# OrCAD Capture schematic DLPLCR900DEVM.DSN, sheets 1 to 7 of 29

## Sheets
1 P28-External Parallel Connector: size A3
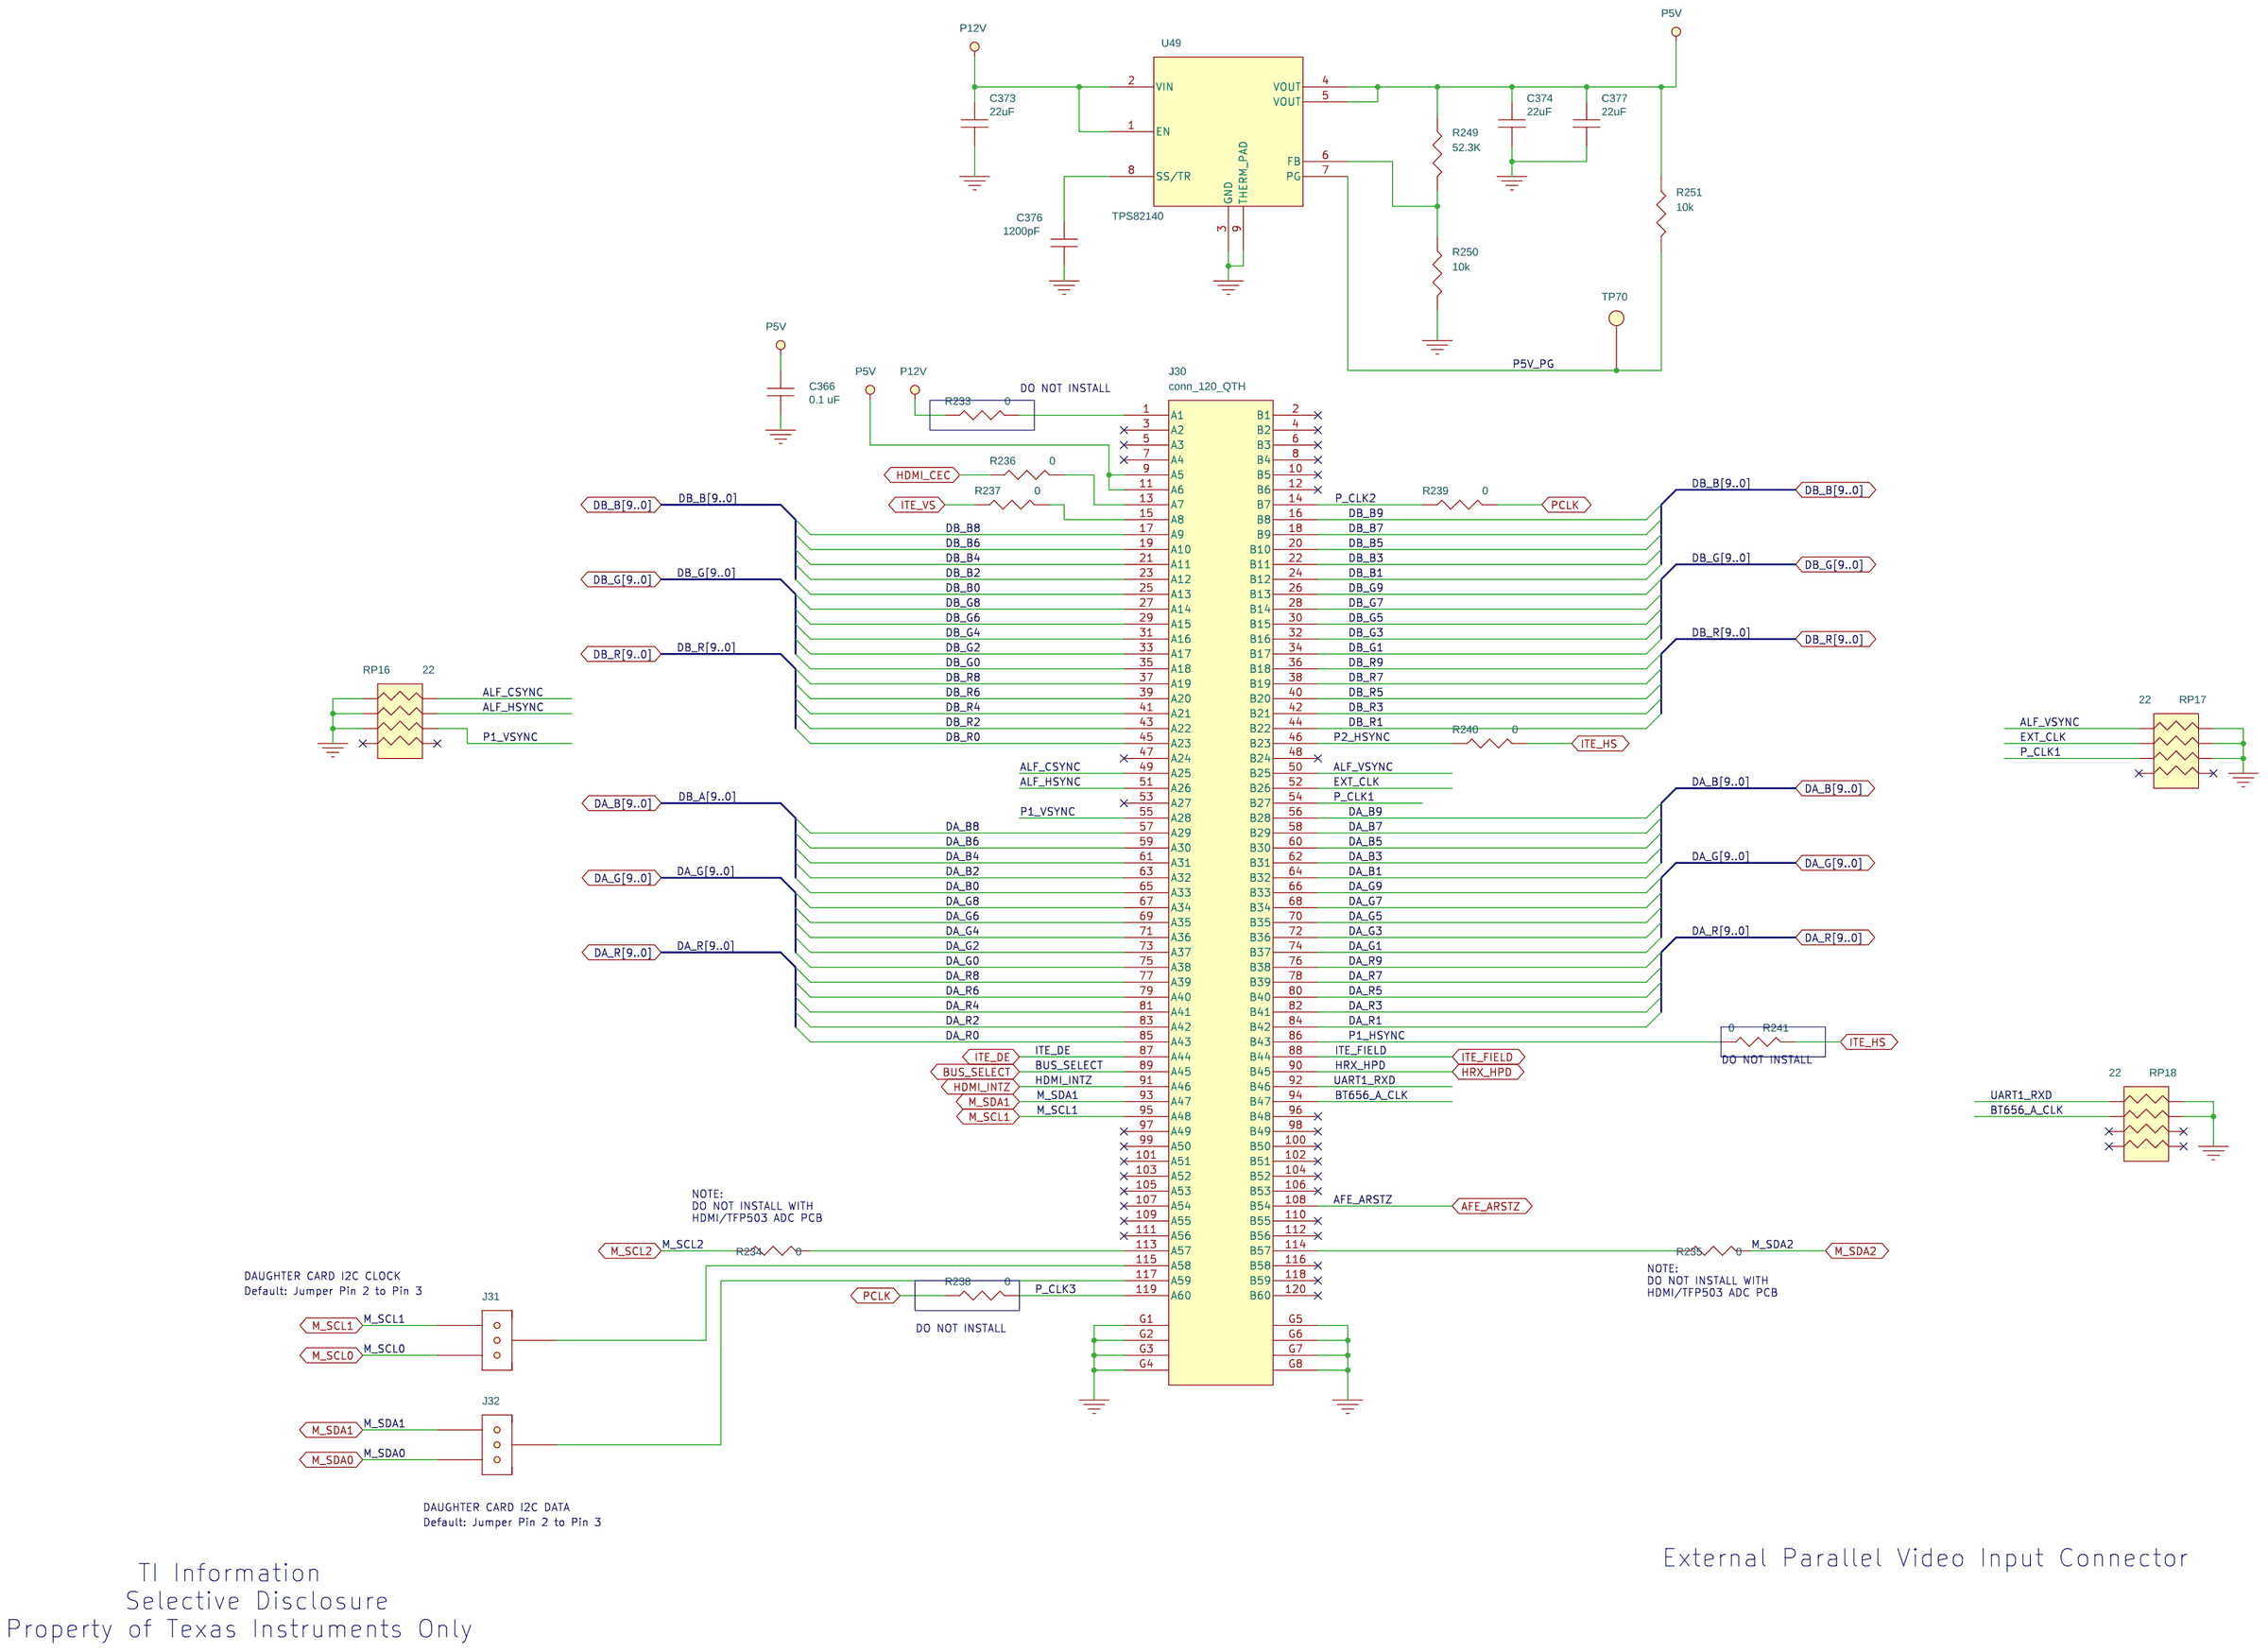
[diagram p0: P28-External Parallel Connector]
2 P02-Import Notice
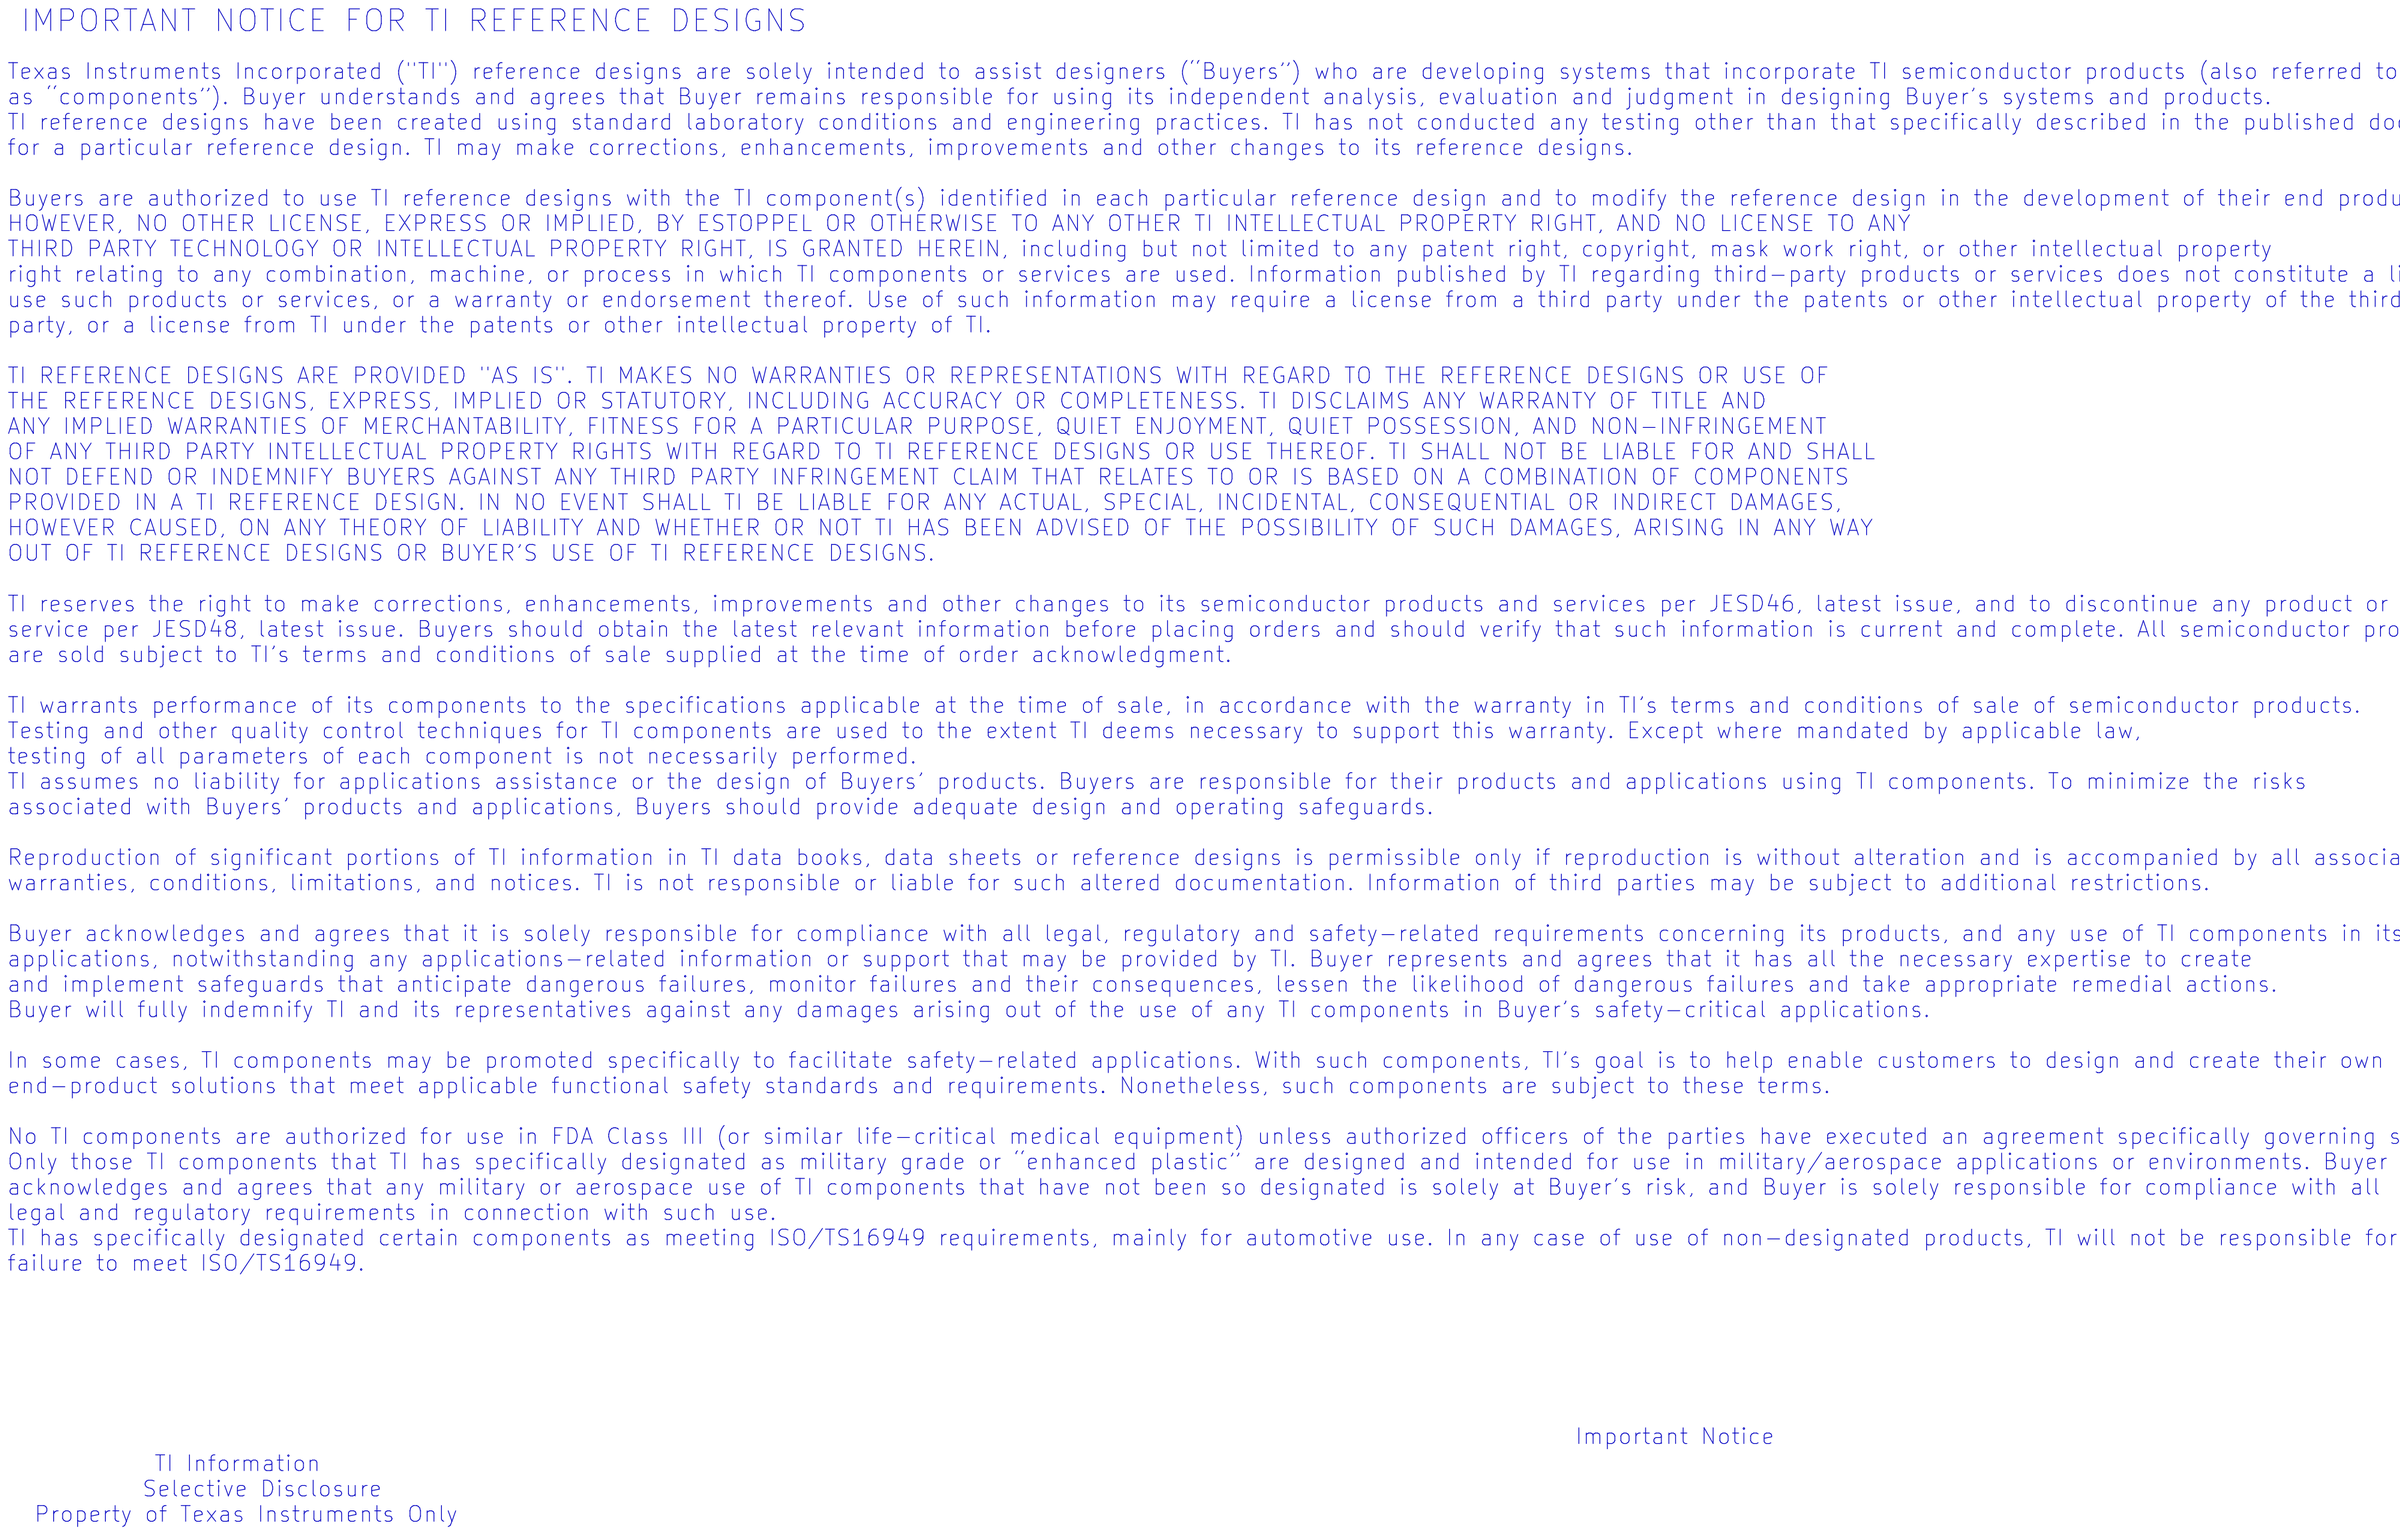
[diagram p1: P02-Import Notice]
3 P25-Power VCCIO & LDO: size A3
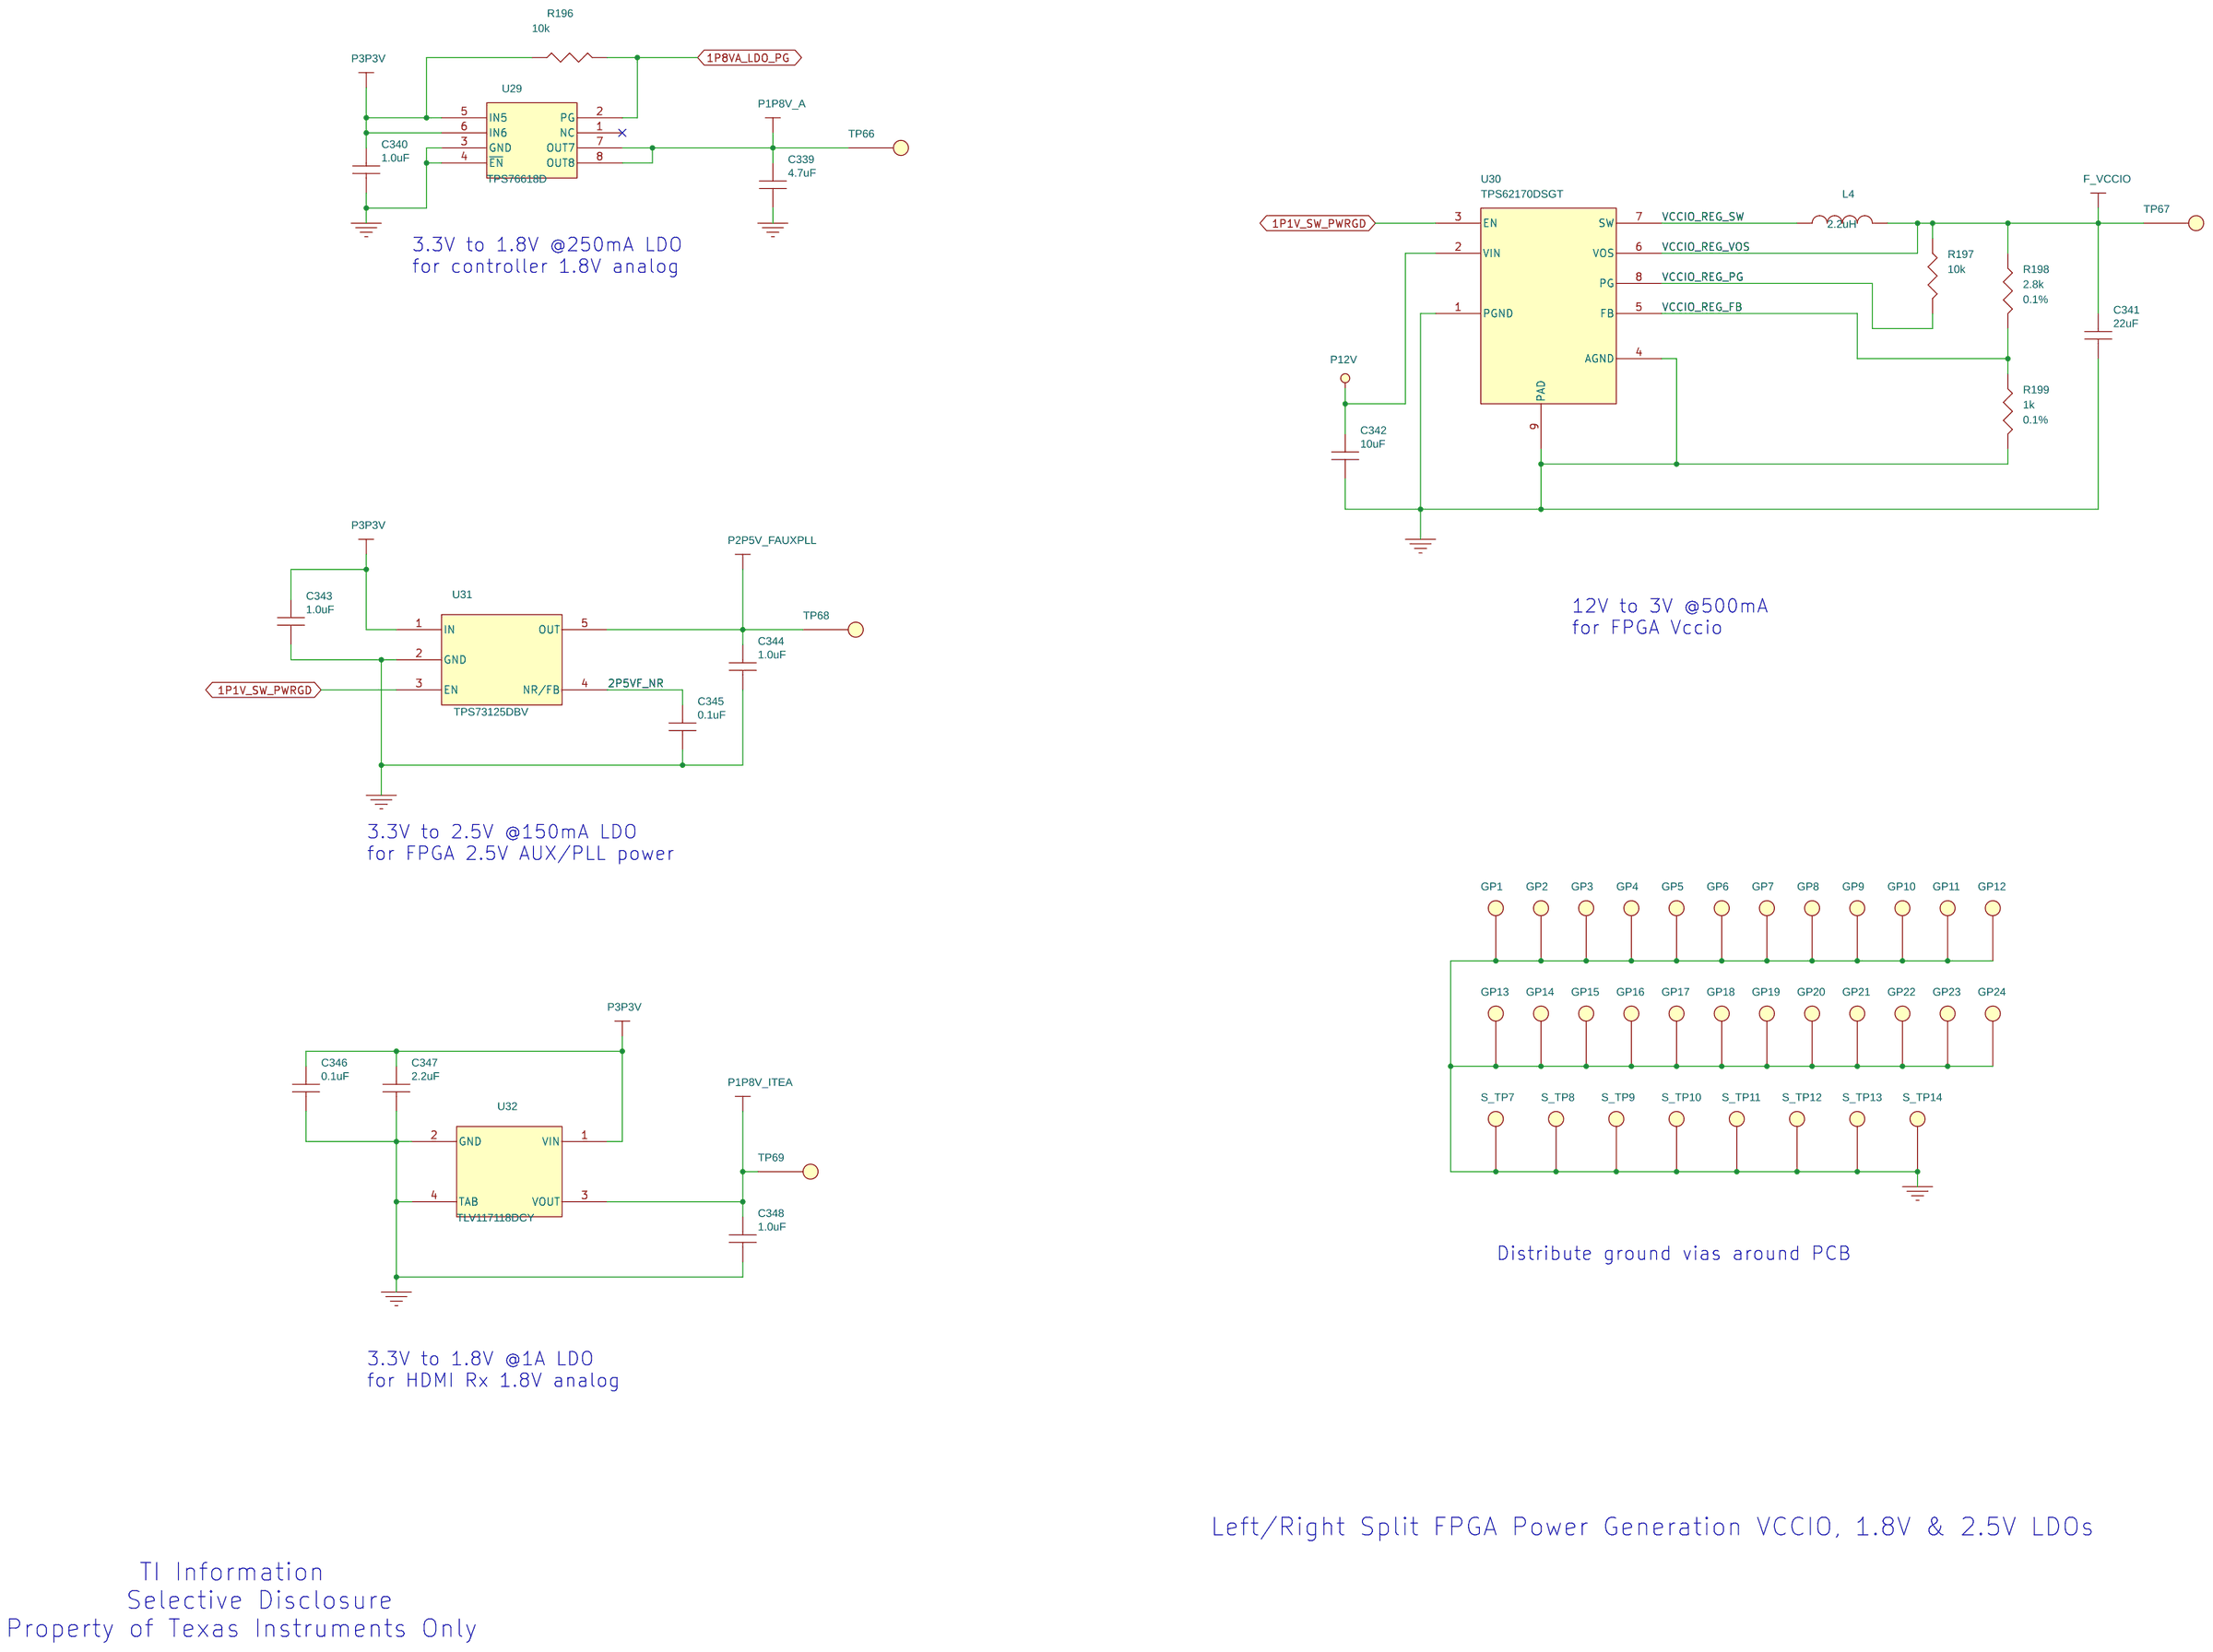
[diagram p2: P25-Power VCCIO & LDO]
4 P10-FPGA Config: size A3
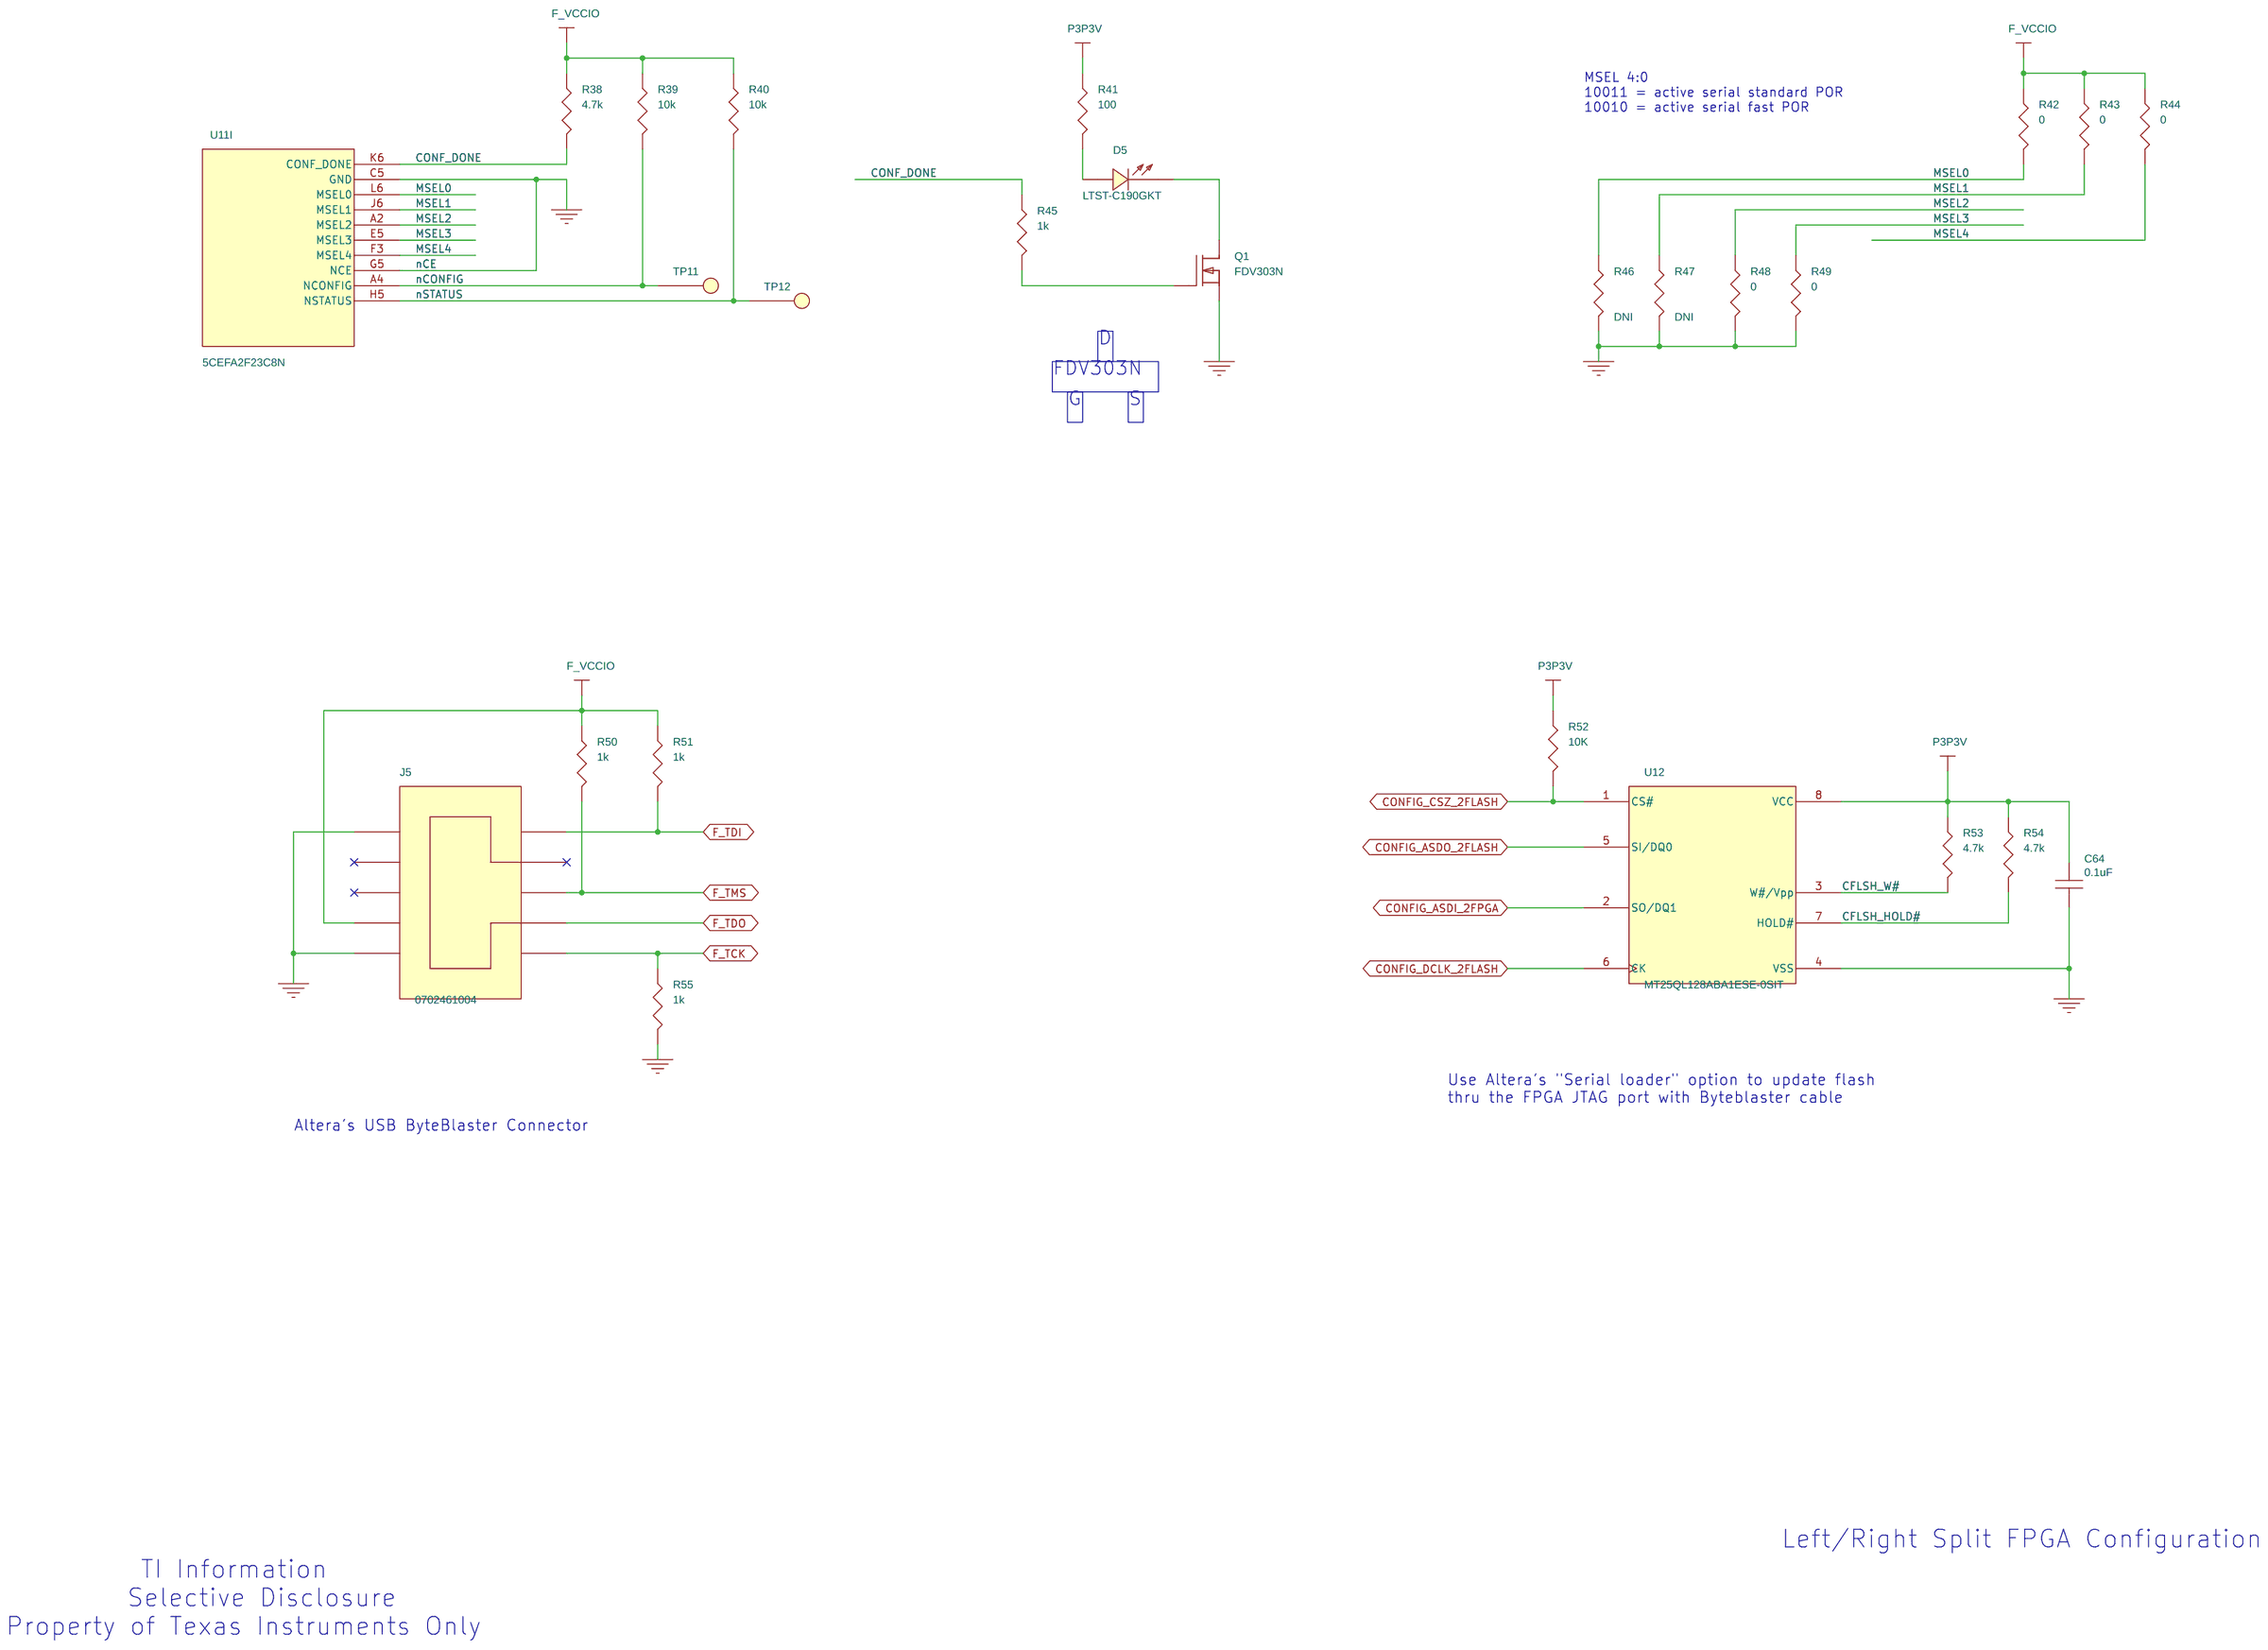
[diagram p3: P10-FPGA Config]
5 P09-FPGA Bank 5A,5B,7A,8A: size A3
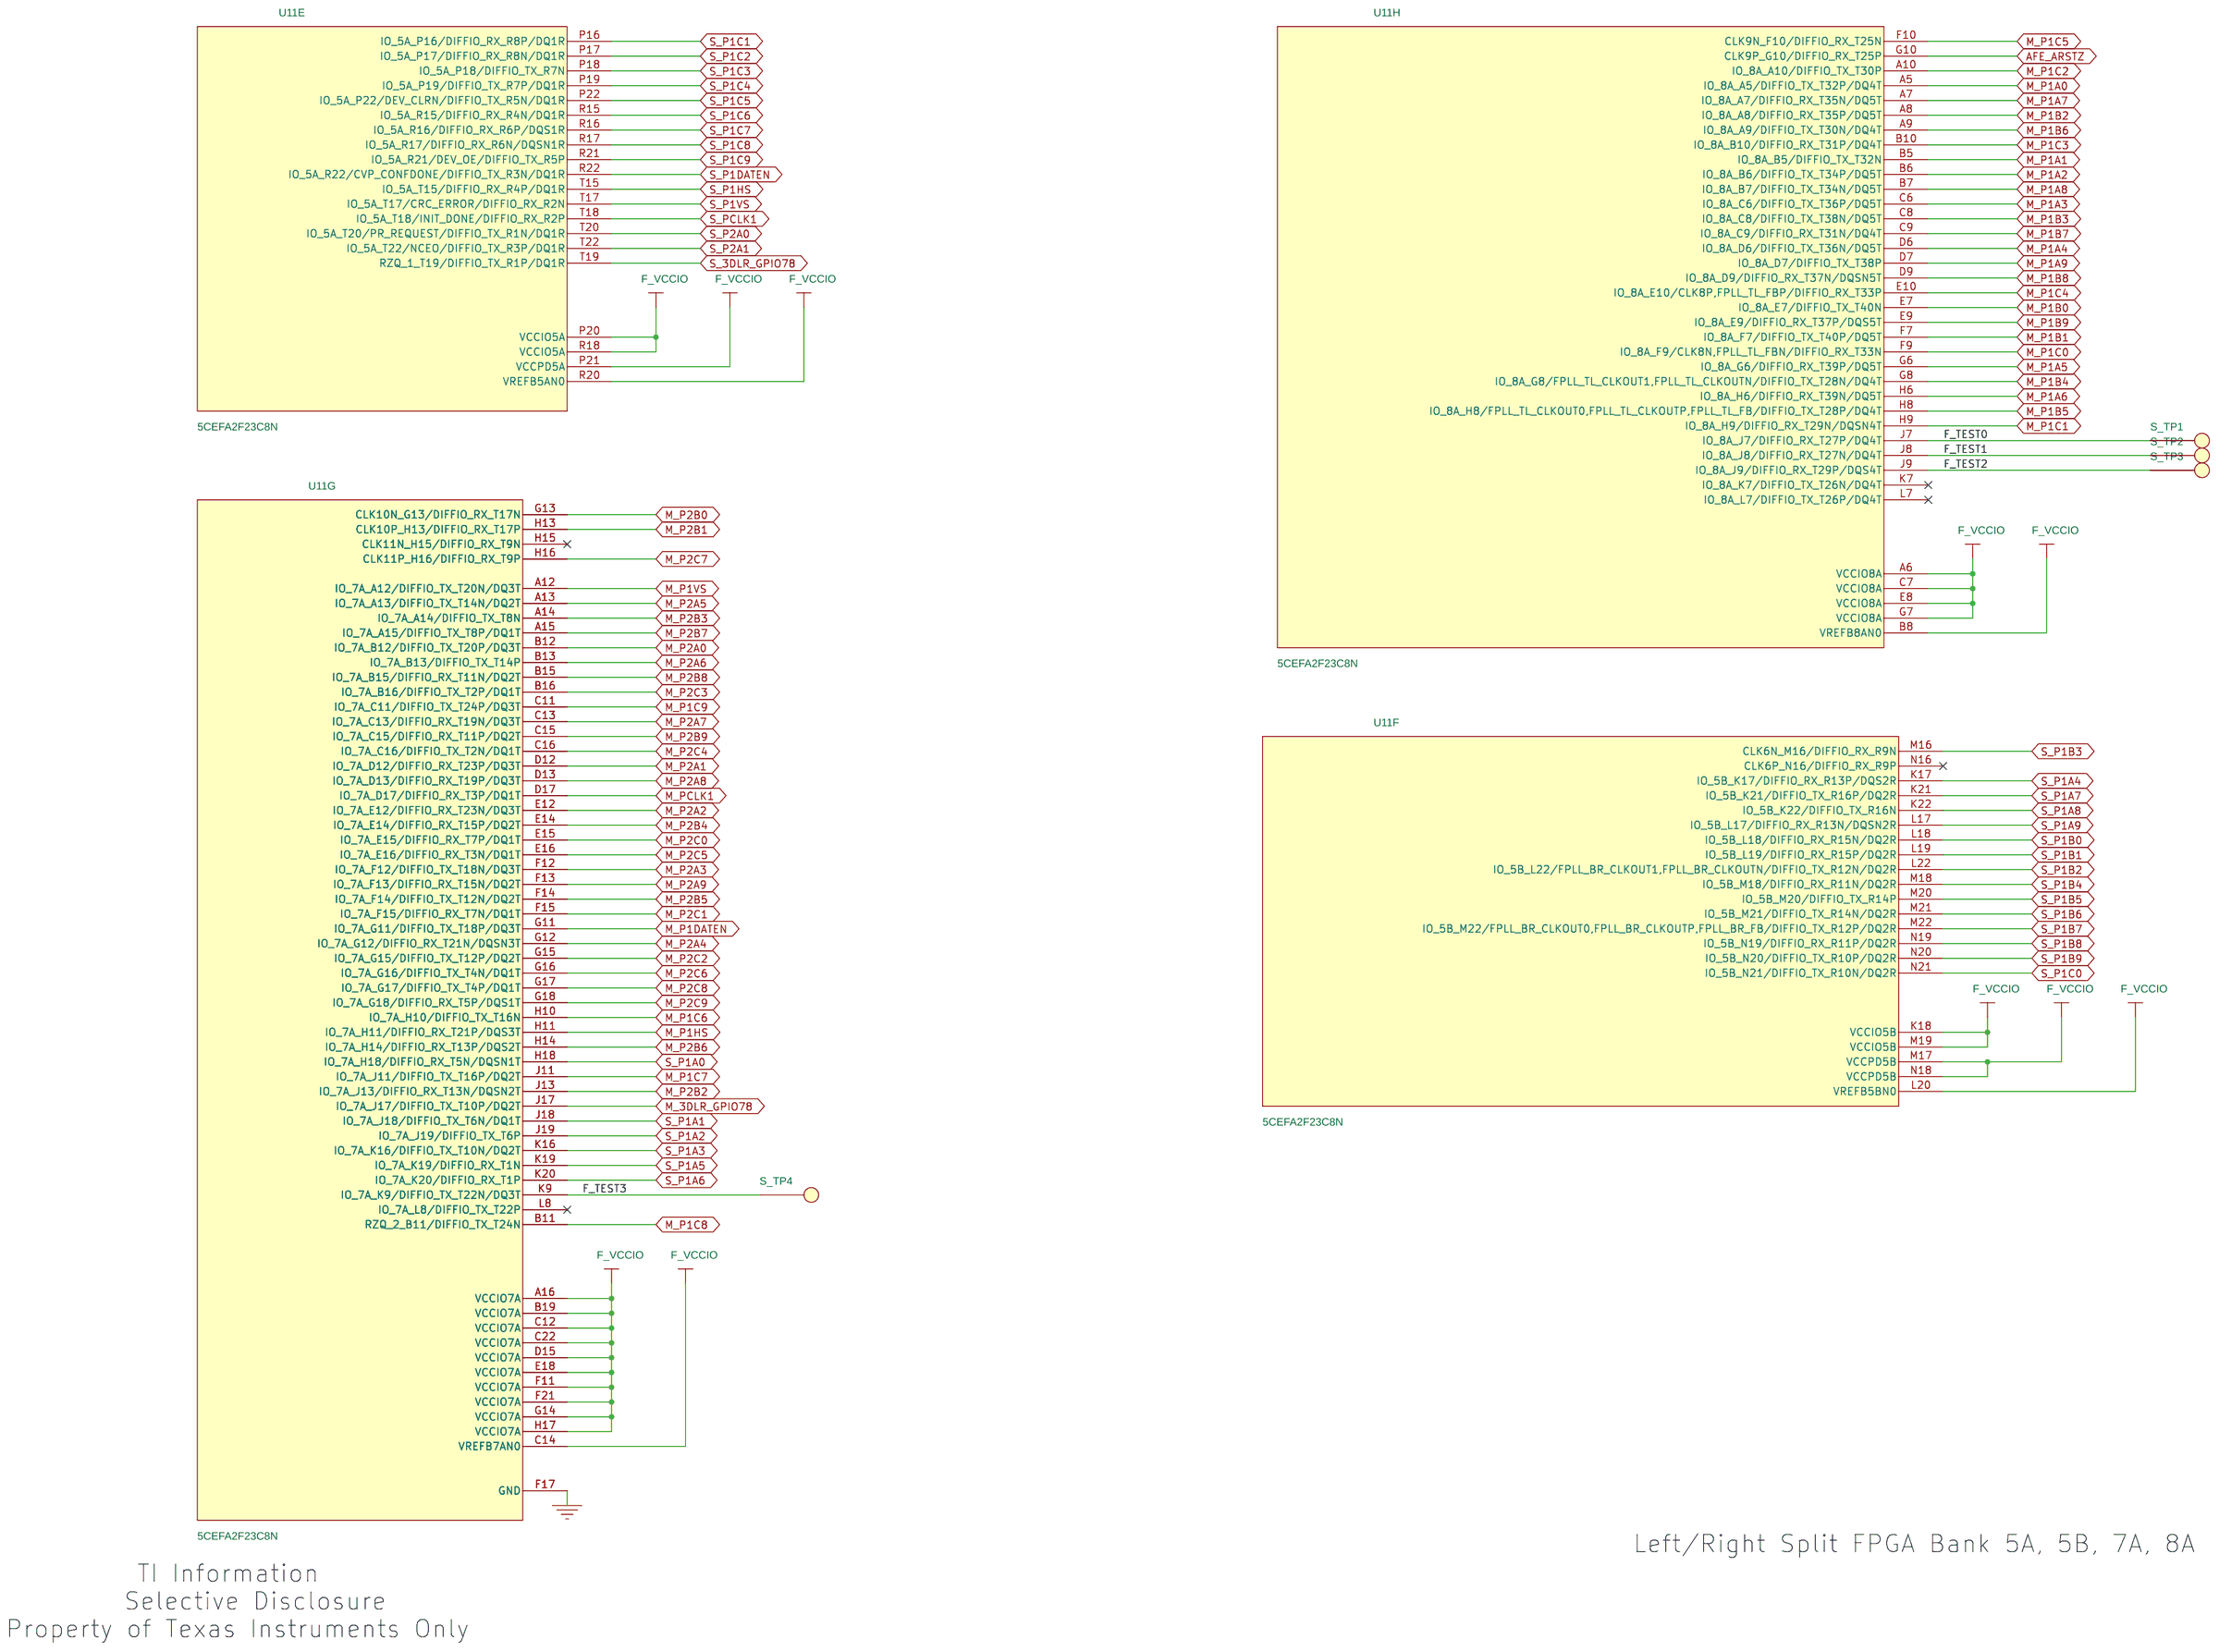
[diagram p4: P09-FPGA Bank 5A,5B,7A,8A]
6 P08-FPGA Bank 2A,3A,3B,4A: size A3
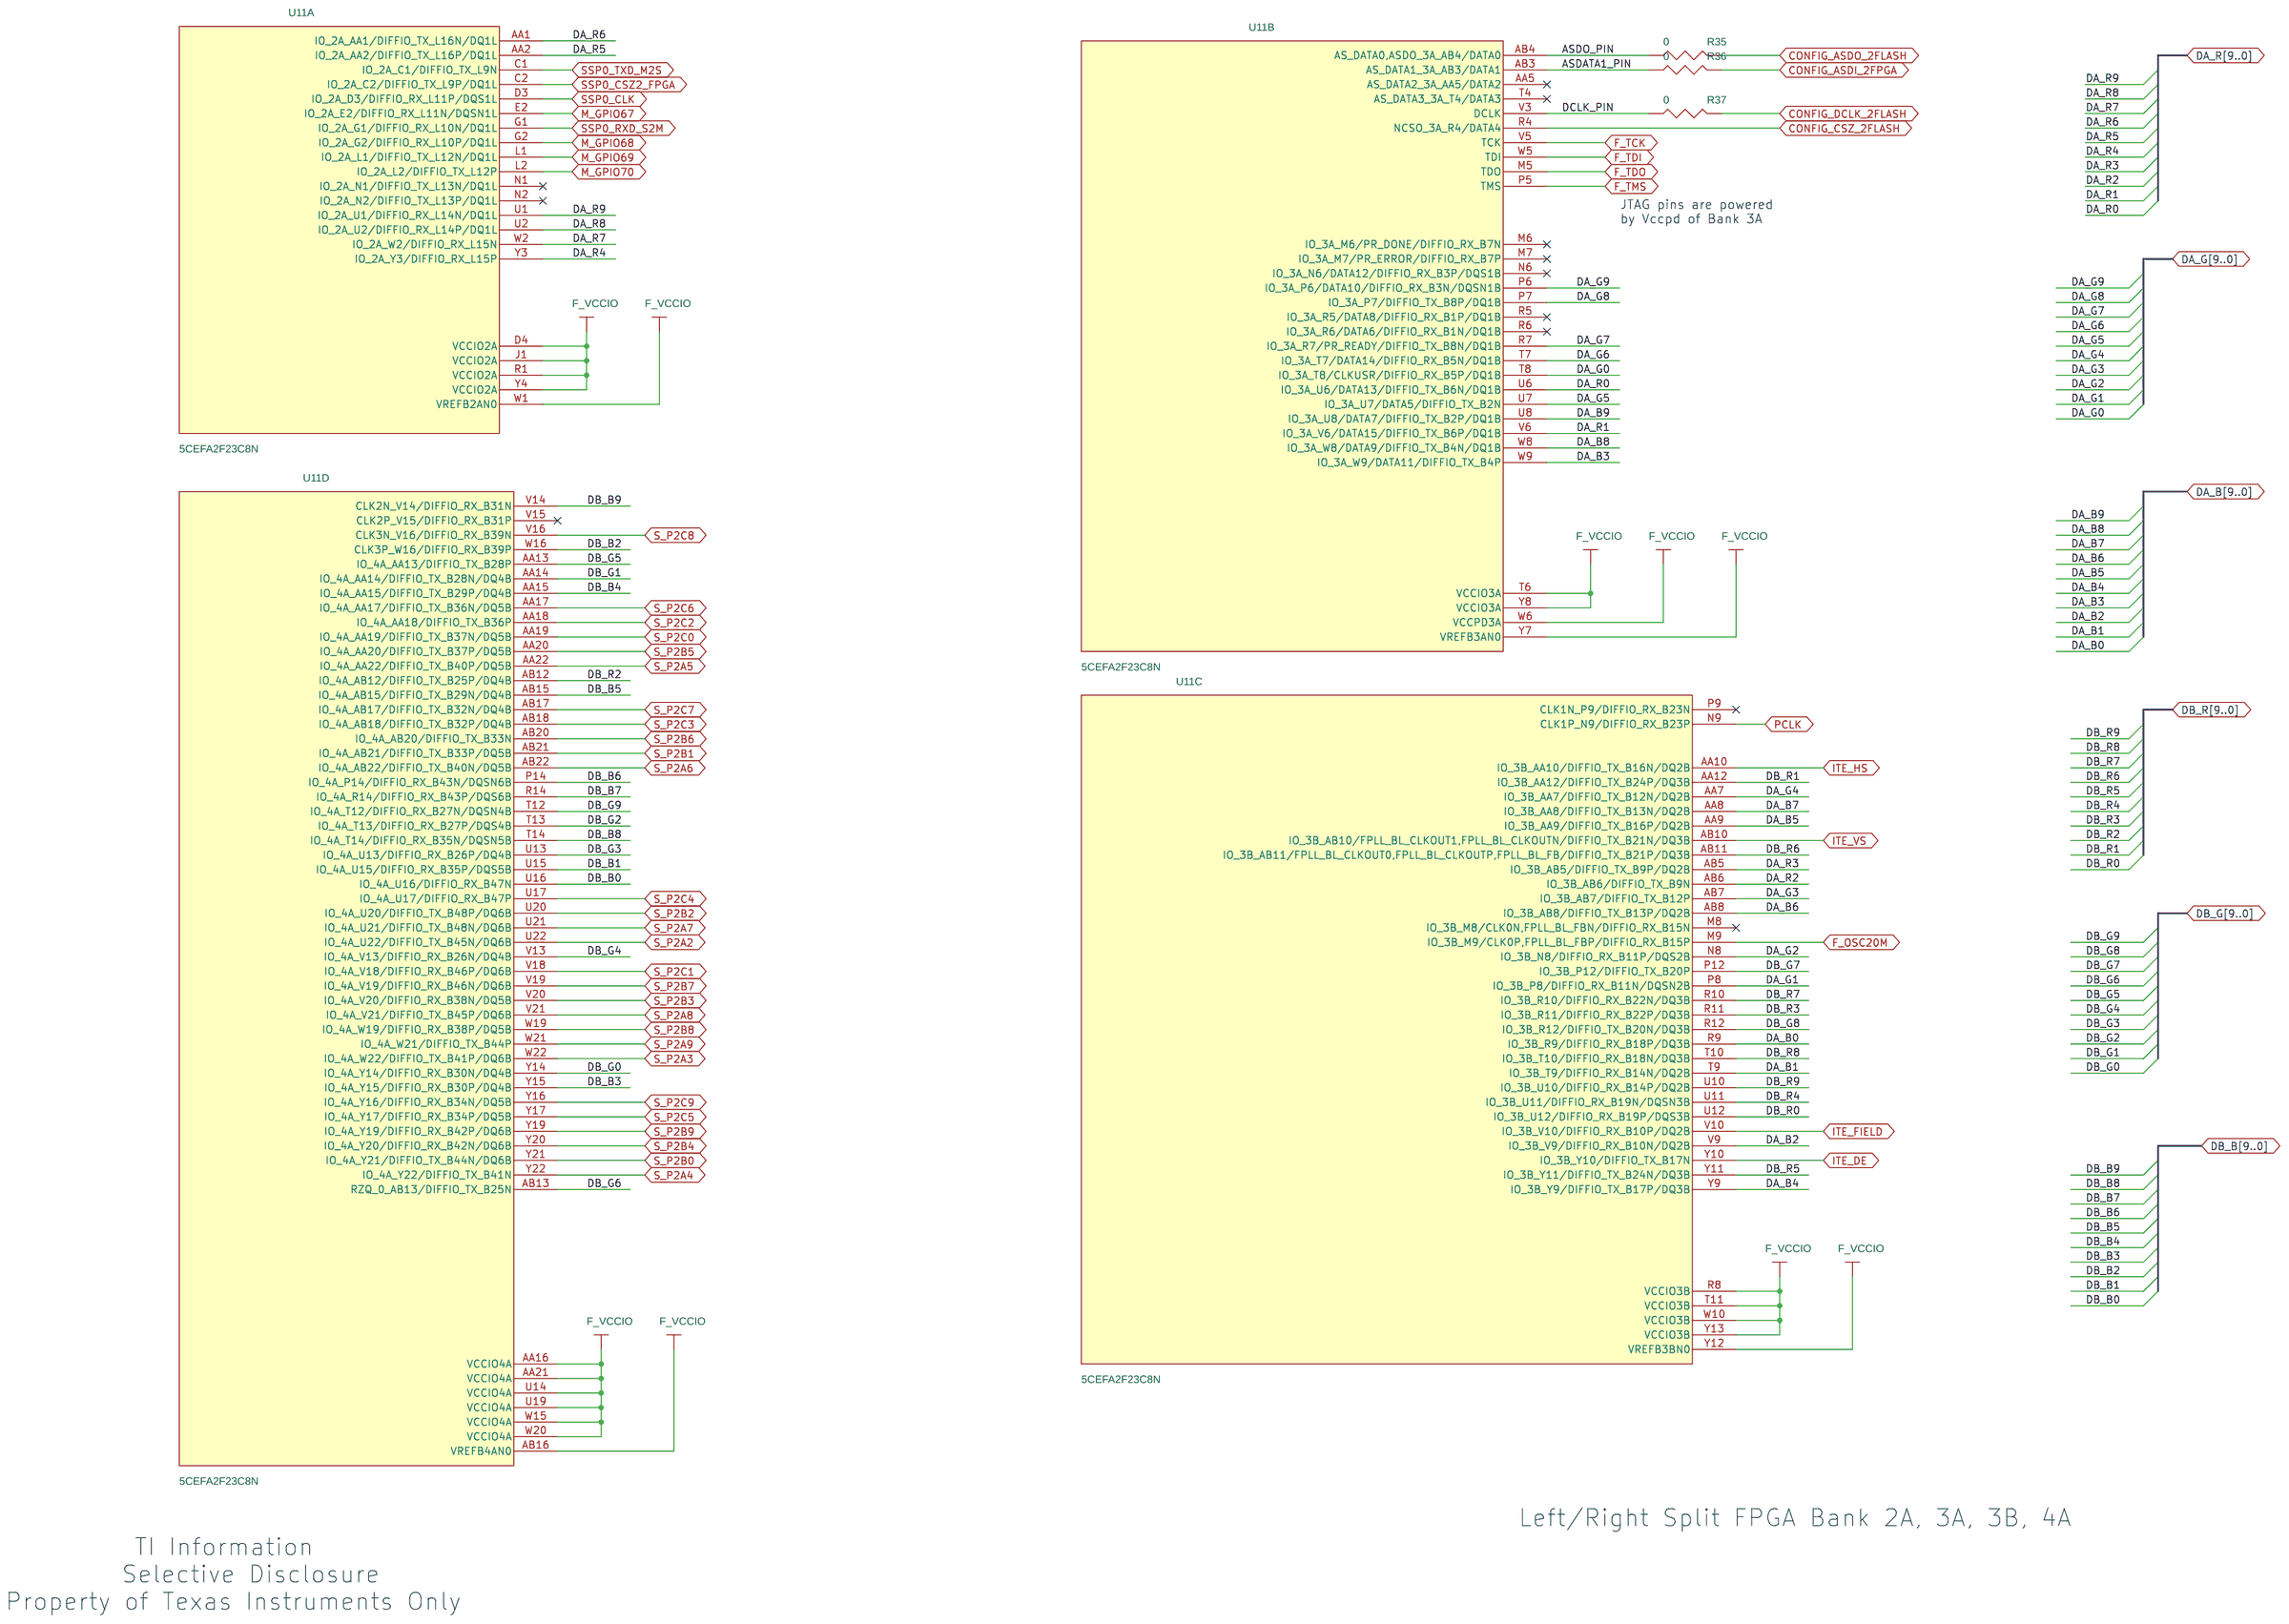
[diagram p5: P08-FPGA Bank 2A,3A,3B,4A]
7 P24-Power 1.1V, 1.8V, 3.3V: size A3
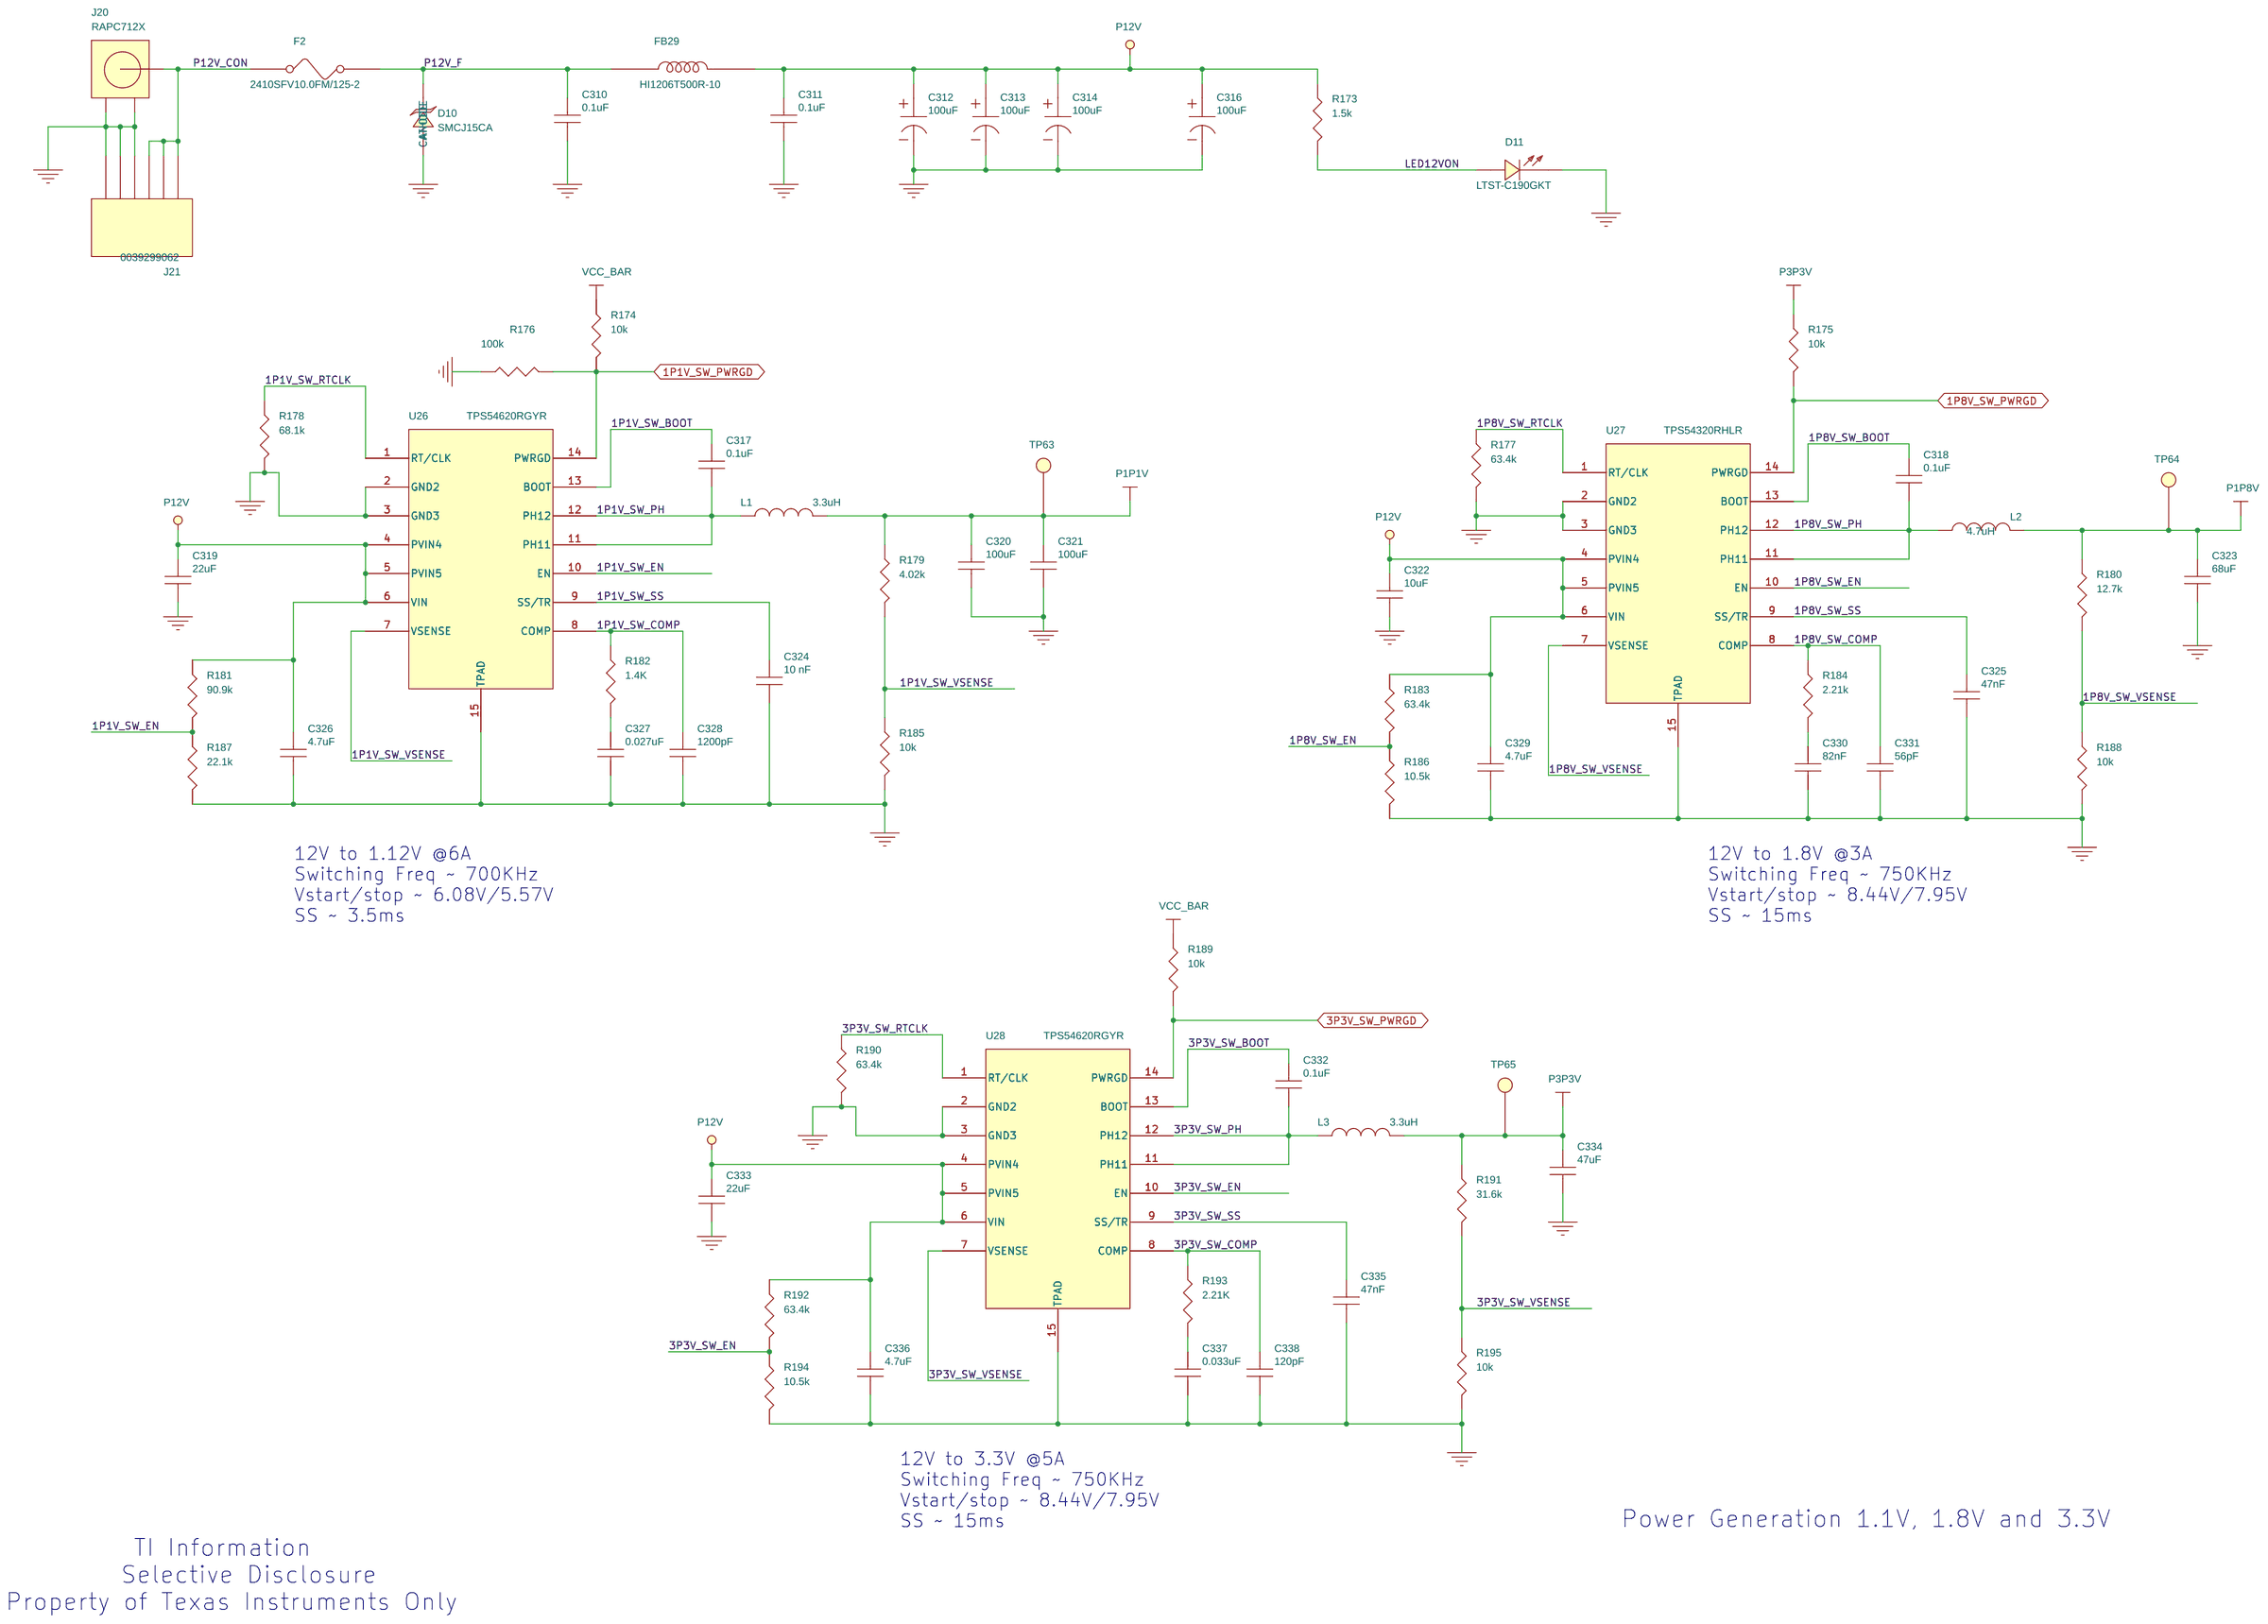
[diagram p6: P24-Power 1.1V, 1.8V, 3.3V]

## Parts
sheet P08-FPGA Bank 2A,3A,3B,4A
R35  0  [0603]
R36  0  [0603]
R37  0  [0603]
sheet P09-FPGA Bank 5A,5B,7A,8A
S_TP1  SMD_Testpoint  [5015pad]
S_TP2  SMD_Testpoint  [5015pad]
S_TP3  SMD_Testpoint  [5015pad]
S_TP4  SMD_Testpoint  [5015pad]
sheet P10-FPGA Config
C64  0.1uF  [0402]
D5  LTST-C190GKT  [0603]
J5  0702461004  [10POS-2ROWS-2p54mm]
Q1  FDV303N  [SOT-23]
R38  4.7k  [0402]
R39  10k  [0402]
R40  10k  [0402]
R41  100  [0603]
R42  0  [0402]
R43  0  [0402]
R44  0  [0402]
R45  1k  [0402]
R46  DNI  [0402]
R47  DNI  [0402]
R48  0  [0402]
R49  0  [0402]
R50  1k  [0402]
R51  1k  [0402]
R52  10K  [0402]
R53  4.7k  [0402]
R54  4.7k  [0402]
R55  1k  [0402]
TP11  Testpoint  [24mil-plated]
TP12  Testpoint  [24mil-plated]
U11  5CEFA2F23C8N  [F484]  (sections A,B,C,D,E,F,G,H,I,J,K)
U12  MT25QL128ABA1ESE-0SIT  [SO8W]
sheet P24-Power 1.1V, 1.8V, 3.3V
C310  0.1uF  [0402]
C311  0.1uF  [0402]
C312  100uF  [2312]
C313  100uF  [2312]
C314  100uF  [2312]
C316  100uF  [2312]
C317  0.1uF  [0402]
C318  0.1uF  [0402]
C319  22uF  [1206]
C320  100uF  [1206]
C321  100uF  [1206]
C322  10uF  [0805]
C323  68uF  [1206]
C324  10 nF  [4002]
C325  47nF  [0402]
C326  4.7uF  [0805]
C327  0.027uF  [0402]
C328  1200pF  [0402]
C329  4.7uF  [0805]
C330  82nF  [0603]
C331  56pF  [0402]
C332  0.1uF  [0402]
C333  22uF  [1206]
C334  47uF  [1210]
C335  47nF  [0402]
C336  4.7uF  [0805]
C337  0.033uF  [0402]
C338  120pF  [0402]
D10  SMCJ15CA  [PN_DIODE]
D11  LTST-C190GKT  [0603]
F2  2410SFV10.0FM/125-2  [2410]
FB29  HI1206T500R-10  [1206]
J20  RAPC712X  [PAPC712Xthruhole]
J21  0039299062  [2x3_4p2mm_thruhole]
L1  3.3uH  [5x5mm]
L2  4.7uH  [4x4mm]
L3  3.3uH  [4x4mm]
R173  1.5k  [0603]
R174  10k  [0402]
R175  10k  [0603]
R176  100k  [0603]
R177  63.4k  [0402]
R178  68.1k  [0402]
R179  4.02k  [0402]
R180  12.7k  [0603]
R181  90.9k  [0402]
R182  1.4K  [0603]
R183  63.4k  [0402]
R184  2.21k  [0402]
R185  10k  [0402]
R186  10.5k  [0402]
R187  22.1k  [0402]
R188  10k  [0402]
R189  10k  [0402]
R190  63.4k  [0402]
R191  31.6k  [0402]
R192  63.4k  [0402]
R193  2.21K  [0402]
R194  10.5k  [0402]
R195  10k  [0402]
TP63  Testpoint  [24mil-plated]
TP64  Testpoint  [24mil-plated]
TP65  Testpoint  [24mil-plated]
U26  TPS54620RGYR  [14-VFQFN]
U27  TPS54320RHLR  [14-VFQFN]
U28  TPS54620RGYR  [14-VFQFN]
sheet P25-Power VCCIO & LDO
C339  4.7uF  [0603]
C340  1.0uF  [0402]
C341  22uF  [0805]
C342  10uF  [0805]
C343  1.0uF  [0402]
C344  1.0uF  [0402]
C345  0.1uF  [0402]
C346  0.1uF  [0402]
C347  2.2uF  [0603]
C348  1.0uF  [0402]
GP1  Ground point  [24mil-plated]
GP2  Ground point  [24mil-plated]
GP3  Ground point  [24mil-plated]
GP4  Ground point  [24mil-plated]
GP5  Ground point  [24mil-plated]
GP6  Ground point  [24mil-plated]
GP7  Ground point  [24mil-plated]
GP8  Ground point  [24mil-plated]
GP9  Ground point  [24mil-plated]
GP10  Ground point  [24mil-plated]
GP11  Ground point  [24mil-plated]
GP12  Ground point  [24mil-plated]
GP13  Ground point  [24mil-plated]
GP14  Ground point  [24mil-plated]
GP15  Ground point  [24mil-plated]
GP16  Ground point  [24mil-plated]
GP17  Ground point  [24mil-plated]
GP18  Ground point  [24mil-plated]
GP19  Ground point  [24mil-plated]
GP20  Ground point  [24mil-plated]
GP21  Ground point  [24mil-plated]
GP22  Ground point  [24mil-plated]
GP23  Ground point  [24mil-plated]
GP24  Ground point  [24mil-plated]
L4  2.2uH  [4x4mm]
R196  10k  [0603]
R197  10k  [0402]
R198  2.8k  [0402]
R199  1k  [0603]
S_TP7  SMD_Testpoint  [5015pad]
S_TP8  SMD_Testpoint  [5015pad]
S_TP9  SMD_Testpoint  [5015pad]
S_TP10  SMD_Testpoint  [5015pad]
S_TP11  SMD_Testpoint  [5015pad]
S_TP12  SMD_Testpoint  [5015pad]
S_TP13  SMD_Testpoint  [5015pad]
S_TP14  SMD_Testpoint  [5015pad]
TP66  Testpoint  [24mil-plated]
TP67  Testpoint  [24mil-plated]
TP68  Testpoint  [24mil-plated]
TP69  Testpoint  [24mil-plated]
U29  TPS76618D  [8SOIC]
U30  TPS62170DSGT  [8WSON]
U31  TPS73125DBV  [SOT23-5]
U32  TLV117118DCY  [SOT223]
sheet P28-External Parallel Connector
C366  0.1 uF  [0402]
C373  22uF  [1206]
C374  22uF  [1206]
C376  1200pF  [0402]
C377  22uF  [1206]
J30  conn_120_QTH  [CONN120-QTH_SAMTEC]
J31  JUMPER-1x3  [CONN3-TMM-103-02-G-S_SAM]
J32  JUMPER-1x3  [CONN3-TMM-103-02-G-S_SAM]
R233  0  [0402]
R234  0  [0402]
R235  0  [0402]
R236  0  [0402]
R237  0  [0402]
R238  0  [0402]
R239  0  [0402]
R240  0  [0402]
R241  0  [0402]
R249  52.3K  [0402]
R250  10k  [0402]
R251  10k  [0402]
RP16  22  [0804]
RP17  22  [0804]
RP18  22  [0804]
TP70  Testpoint  [24mil-plated]
U49  TPS82140  [SOIC8-SIL0008D_TI]

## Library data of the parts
R35-R37 = 0.0_OHM_1_10W_0603
S_TP1-S_TP4 S_TP7-S_TP14 = SMD_Testpoint
C64 = CER_0.1UF_16V_10%_X5R_0402: MFG: Samsung; MFG Part Number: CL05A104KO5NNNC
D5 D11 = LED_GREEN_CLEAR_0603
J5 = 10POS_2ROWS_2.54MM_VERT
Q1 = FDV303N_MOSFET_N
R38 R53 R54 = 4.7K_OHM_1_10W_5%_0402
R39 R40 R46 R47 R52 R174 R189 R197 = 10K_OHM_1_10W_5%_0402
R41 = 100_OHM_1_10W_5%_0603
R42-R44 R48 R49 = 0.0_OHM_1_10W_0402
R45 R50 R51 R55 = 1.0K_OHM_1_16W_5%_0402
TP11 TP12 TP63-TP70 = Testpoint
U11 = FPGA_Cyclone5_5CEFA2F23C8N
U12 = Flash_N25Q_SPI_3.3V_32Mb_8SOW
C310 C311 = CER_0.1UF_50V_10%_X7R_0402: MFG: Samsung; MFG Part Number: CL05A104KO5NNNC
C312-C314 C316 = TANT_100UF_25V_10%_2917: MFG Part Number: T491X107K025AT
C317 C318 C332 C345 C346 = CER_0.1UF_25V_10%_X5R_0402
C319 C333 C373 C374 C377 = CER_22UF_25V_10%_X5R_1206: MFG: Samsung; MFG Part Number: CL31A226KAHNNNE
C320 C321 = CER_100UF_6.3V_20%_X5R_1206
C322 C342 = CER_10UF_25V_10%_X5R_0805
C323 = CER_68UF_10V_20%_X5R_1206
C324 = CER_10_nF_25V_10%_X5R_0402: MFG: Samsung; MFG Part Number: CL05B103KA5NNNC
C325 C335 = CER_0.047UF_16V_10%_X7R_0402
C326 C329 C336 = CER_4.7UF_50V_10%_X5R_0805
C327 = CER_0.027UF_16V_10%_X5R_0402
C328 C376 = CER_1200PF_50V_10%_X7R_0402
C330 = CER_0.082UF_50V_10%_X7R_0603
C331 = CER_56PF_50V_5%_NPO_0402
C334 = CER_47UF_16V_20%_X5R_1210
C337 = CER_0.033UF_16V_10%_X7R_0402
C338 = CER_120PF_50V_5%_NP0_0402
D10 = DIODE_TVS
F2 = FUSE_10A_125V_FAST_2410
FB29 = HI1206T500R-10_6A_50_OHM_1206
J20 = CON_PWRJACK3_RAPC712
J21 = PWR_CONN_HEADER_6POS_4.2MM_VERT
L1 = INDUCTOR_3.3UH_8.7A_20%
L2 = INDUCTOR_4.7UH_4.5A_20%
L3 = INDUCTOR_3.3UH_5.5A_20%
R173 = 1.5K_OHM_1_10W_5%_0603
R175 R196 = 10K_OHM_1_10W_5%_0603
R176 = 100K_OHM_1_10W_1%_0603
R177 R183 R190 R192 = 63.4K_OHM_1_10W_1%_0402
R178 = 68.1K_OHM_1_10W_1%_0402
R179 = 4.02K_OHM_1_10W_.1%_0402
R180 = 12.7K_OHM_1_10W_.1%_0603
R181 = 90.9K_OHM_1_10W_1%_0402
R182 = 1.4K_OHM_1_10W_1%_0603
R184 R193 = 2.21K_OHM_1_10W_1%_0402
R185 R188 R195 R250 R251 = 10K_OHM_1_16W_.1%_0402
R186 R194 = 10.5K_OHM_1_10W_1%_0402
R187 = 22.1K_OHM_1_10W_1%_0402
R191 = 31.6K_OHM_1_16W_.1%_0402
U26 U28 = TPS54620
U27 = TPS54320
C339 = CER_4.7UF_16V_20%_X5R_0603
C340 C343 C344 C348 = CER_1.0UF_16V_10%_X5R_0402: MFG: KEMET; MFG Part Number: C0402C105M4PAC7867
C341 = CER_22UF_16V_10%_X5R_0805
C347 = CER_2.2UF_25V_10%_X5R_0603
GP1-GP24 = Ground_point
L4 = INDUCTOR_2.2UH_XFL4020
R198 = 2.8K_OHM_1_16W_.1%_0402: Tolerance: 0.1%
R199 = 1.0K_OHM_1_10W_.1%_0603: Tolerance: 0.1%
U29 = TPS76618_REG_LDO_1.8V_0.25A
U30 = TPS62170_BUCK_SYNC_ADJ_0.5A
U31 = TPS73125DBV_LDO_2.5V_0.15A
U32 = TLV117118DCY_LDO_1.8V_1A_SOT223
C366 = CAP_NP: Capacitor; MFG: KEMET; MFG Part Number: C0402C104K8RACTU; Part Number: C0402C104K8RACTU; RATING: 10V; SOURCE: DIGI 399-3520-1-ND; TOLERANCE: 10%; Type: X7R
J30 = conn_120_QTH: Connector, 120 pin; MFG: SAMTEC; MFG Part Number: QTH-060-05-F-D-A; Part Number: QTH-060-05-F-D-A; SOURCE: SAMTEC
J31 J32 = JUMPER-1x3: Jumper, 1x3; MFG: HARWIN; MFG Part Number: M22-2510305; Part Number: M22-2510305; SOURCE: DIGI 952-1312-ND
R233 R238 R241 = R: Resistor; DNI: DNI; ICA_MFR_NAME: PANASONIC; ICA_PARTNUM: $$1785048$$ERJ-3GSYJ102; MFG: PANASONIC; MFG Part Number: ERJ-2GE0R00X; Part Number: ERJ-2GE0R00X; RATING: 1/10W; SOURCE: DIGI P0.0JCT-ND
R234-R237 R239 R240 = R: Resistor; ICA_MFR_NAME: PANASONIC; ICA_PARTNUM: $$1785048$$ERJ-3GSYJ102; MFG: PANASONIC; MFG Part Number: ERJ-2GE0R00X; Part Number: ERJ-2GE0R00X; RATING: 1/10W; SOURCE: DIGI P0.0JCT-ND
R249 = 10K_OHM_1_16W_.1%_0402: MFG Part Number: ERJ-2RKF5232X; Rating: 1/10W; TOLERANCE: 1%
RP16-RP18 = 22_OHM_ARR_1_32W_5%_0804
U49 = TPS82140: MFG: Texas Instruments; MFG Part Number: TPS82140SILR; PART NUMBER: TPS82140SILR

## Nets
GND: C64.2 C310.2 C311.2 C312.2 C313.2 C314.2 C316.2 C319.2 C320.2 C321.2 C322.2 C323.2 C324.2 C325.2 C326.2 C327.2 C328.2 C329.2 C330.2 C331.2 C333.2 C334.2 C335.2 C336.2 C337.2 C338.2 C339.2 C340.2 C341.2 C342.2 C343.2 C344.2 C345.2 C346.2 C347.2 C348.2 C366.2 C373.2 C374.2 C376.2 C377.2 D10.2(ANODE) D11.1(CATHODE) GP1.1 GP2.1 GP3.1 GP4.1 GP5.1 GP6.1 GP7.1 GP8.1 GP9.1 GP10.1 GP11.1 GP12.1 GP13.1 GP14.1 GP15.1 GP16.1 GP17.1 GP18.1 GP19.1 GP20.1 GP21.1 GP22.1 GP23.1 GP24.1 J5.2 J5.10 J20.2 J20.3 J21.1 J21.2 J21.3 J30.G1 J30.G2 J30.G3 J30.G4 J30.G5 J30.G6 J30.G7 J30.G8 Q1.S R46.2 R47.2 R48.2 R49.2 R55.2 R176.1 R177.2 R178.2 R185.2 R186.2 R187.2 R188.2 R190.2 R194.2 R195.2 R199.2 R250.2 RP16.1 RP16.2 RP16.3 RP17.1 RP17.2 RP17.3 RP18.1 RP18.2 S_TP7.1 S_TP8.1 S_TP9.1 S_TP10.1 S_TP11.1 S_TP12.1 S_TP13.1 S_TP14.1 U11.C5(GND) U11.F17(GND) U11.G5(NCE) U12.4(VSS) U26.2(GND2) U26.3(GND3) U26.15(TPAD) U27.2(GND2) U27.3(GND3) U27.15(TPAD) U28.2(GND2) U28.3(GND3) U28.15(TPAD) U29.3(GND) U29.4(~{EN}) U30.1(PGND) U30.4(AGND) U30.9(PAD) U31.2(GND) U32.2(GND) U32.4(TAB) U49.3(GND) U49.9(THERM_PAD) ; also on sheet 8 9 10 11 13 14 15 16 17 18 19 23 25 26 27 28 29
P5V: C366.1 C374.1 C377.1 J30.9(A5) J30.11(A6) R249.1 R251.1 U49.4(VOUT) U49.5(VOUT)
P5V_PG: R251.2 TP70.1 U49.7(PG)
P12V: C311.1 C312.1 C313.1 C314.1 C316.1 C319.1 C322.1 C326.1 C329.1 C333.1 C336.1 C342.1 C373.1 FB29.2 R173.1 R181.1 R183.1 R192.1 R233.1 U26.4(PVIN4) U26.5(PVIN5) U26.6(VIN) U27.4(PVIN4) U27.5(PVIN5) U27.6(VIN) U28.4(PVIN4) U28.5(PVIN5) U28.6(VIN) U30.2(VIN) U49.1(EN) U49.2(VIN) ; also on sheet 8 13 14
P12V_CON: F2.1 J20.1 J21.4 J21.5 J21.6
P12V_F: C310.1 D10.1(CATHODE) F2.2 FB29.1
VCCIO_REG_FB: R198.2 R199.1 U30.5(FB)
VCCIO_REG_PG: R197.2 U30.8(PG)
VCCIO_REG_SW: L4.1 U30.7(SW)
1P1V_SW_BOOT: C317.1 U26.13(BOOT)
1P1V_SW_COMP: C328.1 R182.1 U26.8(COMP)
1P1V_SW_EN: R181.2 R187.1 U26.10(EN)
1P1V_SW_PH: C317.2 L1.1 U26.11(PH11) U26.12(PH12)
1P1V_SW_PWRGD: R174.2 R176.2 U26.14(PWRGD) U30.3(EN) U31.3(EN) ; also on sheet 14
1P1V_SW_RTCLK: R178.1 U26.1(RT/CLK)
1P1V_SW_SS: C324.1 U26.9(SS/TR)
1P1V_SW_VSENSE: R179.2 R185.1 U26.7(VSENSE)
1P8V_SW_BOOT: C318.1 U27.13(BOOT)
1P8V_SW_COMP: C331.1 R184.1 U27.8(COMP)
1P8V_SW_EN: R183.2 R186.1 U27.10(EN)
1P8V_SW_PH: C318.2 L2.1 U27.11(PH11) U27.12(PH12)
1P8V_SW_PWRGD: R175.2 U27.14(PWRGD) ; also on sheet 14
1P8V_SW_RTCLK: R177.1 U27.1(RT/CLK)
1P8V_SW_SS: C325.1 U27.9(SS/TR)
1P8V_SW_VSENSE: R180.2 R188.1 U27.7(VSENSE)
1P8VA_LDO_PG: R196.2 U29.2(PG) ; also on sheet 14
2P5VF_NR: C345.1 U31.4(NR/FB)
3P3V_SW_BOOT: C332.1 U28.13(BOOT)
3P3V_SW_COMP: C338.1 R193.1 U28.8(COMP)
3P3V_SW_EN: R192.2 R194.1 U28.10(EN)
3P3V_SW_PH: C332.2 L3.1 U28.11(PH11) U28.12(PH12)
3P3V_SW_PWRGD: R189.2 U28.14(PWRGD) ; also on sheet 14
3P3V_SW_RTCLK: R190.1 U28.1(RT/CLK)
3P3V_SW_SS: C335.1 U28.9(SS/TR)
3P3V_SW_VSENSE: R191.2 R195.1 U28.7(VSENSE)
AFE_ARSTZ: J30.108(B54) U11.G10(CLK9P_G10/DIFFIO_RX_T25P) ; also on sheet 19 23
ALF_CSYNC: J30.49(A25) RP16.8
ALF_HSYNC: J30.51(A26) RP16.7
ALF_VSYNC: J30.50(B25) RP17.8
ASDATA1_PIN: R36.1 U11.AB3(AS_DATA1_3A_AB3/DATA1)
ASDO_PIN: R35.1 U11.AB4(AS_DATA0,ASDO_3A_AB4/DATA0)
BT656_A_CLK: J30.94(B47) RP18.7
BUS_SELECT: J30.89(A45) ; also on sheet 15
CFLSH_HOLD#: R54.2 U12.7(HOLD#)
CFLSH_W#: R53.2 U12.3(W#/Vpp)
CONF_DONE: R38.2 R45.1 U11.K6(CONF_DONE)
CONFIG_ASDI_2FPGA: R36.2 U12.2(SO/DQ1)
CONFIG_ASDO_2FLASH: R35.2 U12.5(SI/DQ0)
CONFIG_CSZ_2FLASH: R52.2 U11.R4(NCSO_3A_R4/DATA4) U12.1(CS#)
CONFIG_DCLK_2FLASH: R37.2 U12.6(CK)
DA_B0: J30.65(A33) U11.R9(IO_3B_R9/DIFFIO_RX_B18P/DQ3B) ; also on sheet 23
DA_B1: J30.64(B32) U11.T9(IO_3B_T9/DIFFIO_RX_B14N/DQ2B) ; also on sheet 23
DA_B2: J30.63(A32) U11.V9(IO_3B_V9/DIFFIO_RX_B10N/DQ2B) ; also on sheet 23
DA_B3: J30.62(B31) U11.W9(IO_3A_W9/DATA11/DIFFIO_TX_B4P) ; also on sheet 23
DA_B4: J30.61(A31) U11.Y9(IO_3B_Y9/DIFFIO_TX_B17P/DQ3B) ; also on sheet 23
DA_B5: J30.60(B30) U11.AA9(IO_3B_AA9/DIFFIO_TX_B16P/DQ2B) ; also on sheet 23
DA_B6: J30.59(A30) U11.AB8(IO_3B_AB8/DIFFIO_TX_B13P/DQ2B) ; also on sheet 23
DA_B7: J30.58(B29) U11.AA8(IO_3B_AA8/DIFFIO_TX_B13N/DQ2B) ; also on sheet 23
DA_B8: J30.57(A29) U11.W8(IO_3A_W8/DATA9/DIFFIO_TX_B4N/DQ1B) ; also on sheet 23
DA_B9: J30.56(B28) U11.U8(IO_3A_U8/DATA7/DIFFIO_TX_B2P/DQ1B) ; also on sheet 23
DA_G0: J30.75(A38) U11.T8(IO_3A_T8/CLKUSR/DIFFIO_RX_B5P/DQ1B) ; also on sheet 23
DA_G1: J30.74(B37) U11.P8(IO_3B_P8/DIFFIO_RX_B11N/DQSN2B) ; also on sheet 23
DA_G2: J30.73(A37) U11.N8(IO_3B_N8/DIFFIO_RX_B11P/DQS2B) ; also on sheet 23
DA_G3: J30.72(B36) U11.AB7(IO_3B_AB7/DIFFIO_TX_B12P) ; also on sheet 23
DA_G4: J30.71(A36) U11.AA7(IO_3B_AA7/DIFFIO_TX_B12N/DQ2B) ; also on sheet 23
DA_G5: J30.70(B35) U11.U7(IO_3A_U7/DATA5/DIFFIO_TX_B2N) ; also on sheet 23
DA_G6: J30.69(A35) U11.T7(IO_3A_T7/DATA14/DIFFIO_RX_B5N/DQ1B) ; also on sheet 23
DA_G7: J30.68(B34) U11.R7(IO_3A_R7/PR_READY/DIFFIO_TX_B8N/DQ1B) ; also on sheet 23
DA_G8: J30.67(A34) U11.P7(IO_3A_P7/DIFFIO_TX_B8P/DQ1B) ; also on sheet 23
DA_G9: J30.66(B33) U11.P6(IO_3A_P6/DATA10/DIFFIO_RX_B3N/DQSN1B) ; also on sheet 23
DA_R0: J30.85(A43) U11.U6(IO_3A_U6/DATA13/DIFFIO_TX_B6N/DQ1B) ; also on sheet 23
DA_R1: J30.84(B42) U11.V6(IO_3A_V6/DATA15/DIFFIO_TX_B6P/DQ1B) ; also on sheet 23
DA_R2: J30.83(A42) U11.AB6(IO_3B_AB6/DIFFIO_TX_B9N) ; also on sheet 23
DA_R3: J30.82(B41) U11.AB5(IO_3B_AB5/DIFFIO_TX_B9P/DQ2B) ; also on sheet 23
DA_R4: J30.81(A41) U11.Y3(IO_2A_Y3/DIFFIO_RX_L15P) ; also on sheet 23
DA_R5: J30.80(B40) U11.AA2(IO_2A_AA2/DIFFIO_TX_L16P/DQ1L) ; also on sheet 23
DA_R6: J30.79(A40) U11.AA1(IO_2A_AA1/DIFFIO_TX_L16N/DQ1L) ; also on sheet 23
DA_R7: J30.78(B39) U11.W2(IO_2A_W2/DIFFIO_RX_L15N) ; also on sheet 23
DA_R8: J30.77(A39) U11.U2(IO_2A_U2/DIFFIO_RX_L14P/DQ1L) ; also on sheet 23
DA_R9: J30.76(B38) U11.U1(IO_2A_U1/DIFFIO_RX_L14N/DQ1L) ; also on sheet 23
DB_B0: J30.25(A13) U11.U16(IO_4A_U16/DIFFIO_RX_B47N) ; also on sheet 23
DB_B1: J30.24(B12) U11.U15(IO_4A_U15/DIFFIO_RX_B35P/DQS5B) ; also on sheet 23
DB_B2: J30.23(A12) U11.W16(CLK3P_W16/DIFFIO_RX_B39P) ; also on sheet 23
DB_B3: J30.22(B11) U11.Y15(IO_4A_Y15/DIFFIO_RX_B30P/DQ4B) ; also on sheet 23
DB_B4: J30.21(A11) U11.AA15(IO_4A_AA15/DIFFIO_TX_B29P/DQ4B) ; also on sheet 23
DB_B5: J30.20(B10) U11.AB15(IO_4A_AB15/DIFFIO_TX_B29N/DQ4B) ; also on sheet 23
DB_B6: J30.19(A10) U11.P14(IO_4A_P14/DIFFIO_RX_B43N/DQSN6B) ; also on sheet 23
DB_B7: J30.18(B9) U11.R14(IO_4A_R14/DIFFIO_RX_B43P/DQS6B) ; also on sheet 23
DB_B8: J30.17(A9) U11.T14(IO_4A_T14/DIFFIO_RX_B35N/DQSN5B) ; also on sheet 23
DB_B9: J30.16(B8) U11.V14(CLK2N_V14/DIFFIO_RX_B31N) ; also on sheet 23
DB_G0: J30.35(A18) U11.Y14(IO_4A_Y14/DIFFIO_RX_B30N/DQ4B) ; also on sheet 23
DB_G1: J30.34(B17) U11.AA14(IO_4A_AA14/DIFFIO_TX_B28N/DQ4B) ; also on sheet 23
DB_G2: J30.33(A17) U11.T13(IO_4A_T13/DIFFIO_RX_B27P/DQS4B) ; also on sheet 23
DB_G3: J30.32(B16) U11.U13(IO_4A_U13/DIFFIO_RX_B26P/DQ4B) ; also on sheet 23
DB_G4: J30.31(A16) U11.V13(IO_4A_V13/DIFFIO_RX_B26N/DQ4B) ; also on sheet 23
DB_G5: J30.30(B15) U11.AA13(IO_4A_AA13/DIFFIO_TX_B28P) ; also on sheet 23
DB_G6: J30.29(A15) U11.AB13(RZQ_0_AB13/DIFFIO_TX_B25N) ; also on sheet 23
DB_G7: J30.28(B14) U11.P12(IO_3B_P12/DIFFIO_TX_B20P) ; also on sheet 23
DB_G8: J30.27(A14) U11.R12(IO_3B_R12/DIFFIO_TX_B20N/DQ3B) ; also on sheet 23
DB_G9: J30.26(B13) U11.T12(IO_4A_T12/DIFFIO_RX_B27N/DQSN4B) ; also on sheet 23
DB_R0: J30.45(A23) U11.U12(IO_3B_U12/DIFFIO_RX_B19P/DQS3B) ; also on sheet 23
DB_R1: J30.44(B22) U11.AA12(IO_3B_AA12/DIFFIO_TX_B24P/DQ3B) ; also on sheet 23
DB_R2: J30.43(A22) U11.AB12(IO_4A_AB12/DIFFIO_TX_B25P/DQ4B) ; also on sheet 23
DB_R3: J30.42(B21) U11.R11(IO_3B_R11/DIFFIO_RX_B22P/DQ3B) ; also on sheet 23
DB_R4: J30.41(A21) U11.U11(IO_3B_U11/DIFFIO_RX_B19N/DQSN3B) ; also on sheet 23
DB_R5: J30.40(B20) U11.Y11(IO_3B_Y11/DIFFIO_TX_B24N/DQ3B) ; also on sheet 23
DB_R6: J30.39(A20) U11.AB11(IO_3B_AB11/FPLL_BL_CLKOUT0,FPLL_BL_CLKOUTP,FPLL_BL_FB/DIFFIO_TX_B21P/DQ3B) ; also on sheet 23
DB_R7: J30.38(B19) U11.R10(IO_3B_R10/DIFFIO_RX_B22N/DQ3B) ; also on sheet 23
DB_R8: J30.37(A19) U11.T10(IO_3B_T10/DIFFIO_RX_B18N/DQ3B) ; also on sheet 23
DB_R9: J30.36(B18) U11.U10(IO_3B_U10/DIFFIO_RX_B14P/DQ2B) ; also on sheet 23
DCLK_PIN: R37.1 U11.V3(DCLK)
EXT_CLK: J30.52(B26) RP17.7
F_OSC20M: U11.M9(IO_3B_M9/CLK0P,FPLL_BL_FBP/DIFFIO_RX_B15P) ; also on sheet 14
F_TCK: J5.1 R55.1 U11.V5(TCK)
F_TDI: J5.9 R51.2 U11.W5(TDI)
F_TDO: J5.3 U11.M5(TDO)
F_TEST0: S_TP1.1 U11.J7(IO_8A_J7/DIFFIO_RX_T27P/DQ4T)
F_TEST1: S_TP2.1 U11.J8(IO_8A_J8/DIFFIO_RX_T27N/DQ4T)
F_TEST2: S_TP3.1 U11.J9(IO_8A_J9/DIFFIO_RX_T29P/DQS4T)
F_TEST3: S_TP4.1 U11.K9(IO_7A_K9/DIFFIO_TX_T22N/DQ3T)
F_TMS: J5.5 R50.2 U11.P5(TMS)
F_VCCIO: C341.1 J5.4 L4.2 R38.1 R39.1 R40.1 R42.1 R43.1 R44.1 R50.1 R51.1 R197.1 R198.1 TP67.1 U11.A6(VCCIO8A) U11.A16(VCCIO7A) U11.AA16(VCCIO4A) U11.AA21(VCCIO4A) U11.AB16(VREFB4AN0) U11.B8(VREFB8AN0) U11.B19(VCCIO7A) U11.C7(VCCIO8A) U11.C12(VCCIO7A) U11.C14(VREFB7AN0) U11.C22(VCCIO7A) U11.D4(VCCIO2A) U11.D15(VCCIO7A) U11.E8(VCCIO8A) U11.E18(VCCIO7A) U11.F11(VCCIO7A) U11.F21(VCCIO7A) U11.G7(VCCIO8A) U11.G14(VCCIO7A) U11.H17(VCCIO7A) U11.J1(VCCIO2A) U11.K18(VCCIO5B) U11.L20(VREFB5BN0) U11.M17(VCCPD5B) U11.M19(VCCIO5B) U11.N18(VCCPD5B) U11.P20(VCCIO5A) U11.P21(VCCPD5A) U11.R1(VCCIO2A) U11.R8(VCCIO3B) U11.R18(VCCIO5A) U11.R20(VREFB5AN0) U11.T6(VCCIO3A) U11.T11(VCCIO3B) U11.U14(VCCIO4A) U11.U19(VCCIO4A) U11.W1(VREFB2AN0) U11.W6(VCCPD3A) U11.W10(VCCIO3B) U11.W15(VCCIO4A) U11.W20(VCCIO4A) U11.Y4(VCCIO2A) U11.Y7(VREFB3AN0) U11.Y8(VCCIO3A) U11.Y12(VREFB3BN0) U11.Y13(VCCIO3B) U30.6(VOS) ; also on sheet 26
HDMI_CEC: R236.1 ; also on sheet 19
HDMI_INTZ: J30.91(A46) ; also on sheet 19 23
HRX_HPD: J30.90(B45) ; also on sheet 29
ITE_DE: J30.87(A44) U11.Y10(IO_3B_Y10/DIFFIO_TX_B17N) ; also on sheet 23
ITE_FIELD: J30.88(B44) U11.V10(IO_3B_V10/DIFFIO_RX_B10P/DQ2B) ; also on sheet 23
ITE_HS: R240.2 R241.1 U11.AA10(IO_3B_AA10/DIFFIO_TX_B16N/DQ2B) ; also on sheet 23
ITE_VS: R237.1 U11.AB10(IO_3B_AB10/FPLL_BL_CLKOUT1,FPLL_BL_CLKOUTN/DIFFIO_TX_B21N/DQ3B) ; also on sheet 23
LED12VON: D11.2(ANODE) R173.2
M_3DLR_GPIO78: U11.J17(IO_7A_J17/DIFFIO_TX_T10P/DQ2T) ; also on sheet 19
M_GPIO67: U11.E2(IO_2A_E2/DIFFIO_RX_L11N/DQSN1L) ; also on sheet 15
M_GPIO68: U11.G2(IO_2A_G2/DIFFIO_RX_L10P/DQ1L) ; also on sheet 15
M_GPIO69: U11.L1(IO_2A_L1/DIFFIO_TX_L12N/DQ1L) ; also on sheet 15
M_GPIO70: U11.L2(IO_2A_L2/DIFFIO_TX_L12P) ; also on sheet 15
M_P1A0: U11.A5(IO_8A_A5/DIFFIO_TX_T32P/DQ4T) ; also on sheet 19
M_P1A1: U11.B5(IO_8A_B5/DIFFIO_TX_T32N) ; also on sheet 19
M_P1A2: U11.B6(IO_8A_B6/DIFFIO_TX_T34P/DQ5T) ; also on sheet 19
M_P1A3: U11.C6(IO_8A_C6/DIFFIO_TX_T36P/DQ5T) ; also on sheet 19
M_P1A4: U11.D6(IO_8A_D6/DIFFIO_TX_T36N/DQ5T) ; also on sheet 19
M_P1A5: U11.G6(IO_8A_G6/DIFFIO_RX_T39P/DQ5T) ; also on sheet 19
M_P1A6: U11.H6(IO_8A_H6/DIFFIO_RX_T39N/DQ5T) ; also on sheet 19
M_P1A7: U11.A7(IO_8A_A7/DIFFIO_RX_T35N/DQ5T) ; also on sheet 19
M_P1A8: U11.B7(IO_8A_B7/DIFFIO_TX_T34N/DQ5T) ; also on sheet 19
M_P1A9: U11.D7(IO_8A_D7/DIFFIO_TX_T38P) ; also on sheet 19
M_P1B0: U11.E7(IO_8A_E7/DIFFIO_TX_T40N) ; also on sheet 19
M_P1B1: U11.F7(IO_8A_F7/DIFFIO_TX_T40P/DQ5T) ; also on sheet 19
M_P1B2: U11.A8(IO_8A_A8/DIFFIO_RX_T35P/DQ5T) ; also on sheet 19
M_P1B3: U11.C8(IO_8A_C8/DIFFIO_TX_T38N/DQ5T) ; also on sheet 19
M_P1B4: U11.G8(IO_8A_G8/FPLL_TL_CLKOUT1,FPLL_TL_CLKOUTN/DIFFIO_TX_T28N/DQ4T) ; also on sheet 19
M_P1B5: U11.H8(IO_8A_H8/FPLL_TL_CLKOUT0,FPLL_TL_CLKOUTP,FPLL_TL_FB/DIFFIO_TX_T28P/DQ4T) ; also on sheet 19
M_P1B6: U11.A9(IO_8A_A9/DIFFIO_TX_T30N/DQ4T) ; also on sheet 19
M_P1B7: U11.C9(IO_8A_C9/DIFFIO_RX_T31N/DQ4T) ; also on sheet 19
M_P1B8: U11.D9(IO_8A_D9/DIFFIO_RX_T37N/DQSN5T) ; also on sheet 19
M_P1B9: U11.E9(IO_8A_E9/DIFFIO_RX_T37P/DQS5T) ; also on sheet 19
M_P1C0: U11.F9(IO_8A_F9/CLK8N,FPLL_TL_FBN/DIFFIO_RX_T33N) ; also on sheet 19
M_P1C1: U11.H9(IO_8A_H9/DIFFIO_RX_T29N/DQSN4T) ; also on sheet 19
M_P1C2: U11.A10(IO_8A_A10/DIFFIO_TX_T30P) ; also on sheet 19
M_P1C3: U11.B10(IO_8A_B10/DIFFIO_RX_T31P/DQ4T) ; also on sheet 19
M_P1C4: U11.E10(IO_8A_E10/CLK8P,FPLL_TL_FBP/DIFFIO_RX_T33P) ; also on sheet 19
M_P1C5: U11.F10(CLK9N_F10/DIFFIO_RX_T25N) ; also on sheet 19
M_P1C6: U11.H10(IO_7A_H10/DIFFIO_TX_T16N) ; also on sheet 19
M_P1C7: U11.J11(IO_7A_J11/DIFFIO_TX_T16P/DQ2T) ; also on sheet 19
M_P1C8: U11.B11(RZQ_2_B11/DIFFIO_TX_T24N) ; also on sheet 19
M_P1C9: U11.C11(IO_7A_C11/DIFFIO_TX_T24P/DQ3T) ; also on sheet 19
M_P1DATEN: U11.G11(IO_7A_G11/DIFFIO_TX_T18P/DQ3T) ; also on sheet 19
M_P1HS: U11.H11(IO_7A_H11/DIFFIO_RX_T21P/DQS3T) ; also on sheet 19
M_P1VS: U11.A12(IO_7A_A12/DIFFIO_TX_T20N/DQ3T) ; also on sheet 19
M_P2A0: U11.B12(IO_7A_B12/DIFFIO_TX_T20P/DQ3T) ; also on sheet 19
M_P2A1: U11.D12(IO_7A_D12/DIFFIO_RX_T23P/DQ3T) ; also on sheet 19
M_P2A2: U11.E12(IO_7A_E12/DIFFIO_RX_T23N/DQ3T) ; also on sheet 19
M_P2A3: U11.F12(IO_7A_F12/DIFFIO_TX_T18N/DQ3T) ; also on sheet 19
M_P2A4: U11.G12(IO_7A_G12/DIFFIO_RX_T21N/DQSN3T) ; also on sheet 19
M_P2A5: U11.A13(IO_7A_A13/DIFFIO_TX_T14N/DQ2T) ; also on sheet 19
M_P2A6: U11.B13(IO_7A_B13/DIFFIO_TX_T14P) ; also on sheet 19
M_P2A7: U11.C13(IO_7A_C13/DIFFIO_RX_T19N/DQ3T) ; also on sheet 19
M_P2A8: U11.D13(IO_7A_D13/DIFFIO_RX_T19P/DQ3T) ; also on sheet 19
M_P2A9: U11.F13(IO_7A_F13/DIFFIO_RX_T15N/DQ2T) ; also on sheet 19
M_P2B0: U11.G13(CLK10N_G13/DIFFIO_RX_T17N) ; also on sheet 19
M_P2B1: U11.H13(CLK10P_H13/DIFFIO_RX_T17P) ; also on sheet 19
M_P2B2: U11.J13(IO_7A_J13/DIFFIO_RX_T13N/DQSN2T) ; also on sheet 19
M_P2B3: U11.A14(IO_7A_A14/DIFFIO_TX_T8N) ; also on sheet 19
M_P2B4: U11.E14(IO_7A_E14/DIFFIO_RX_T15P/DQ2T) ; also on sheet 19
M_P2B5: U11.F14(IO_7A_F14/DIFFIO_TX_T12N/DQ2T) ; also on sheet 19
M_P2B6: U11.H14(IO_7A_H14/DIFFIO_RX_T13P/DQS2T) ; also on sheet 19
M_P2B7: U11.A15(IO_7A_A15/DIFFIO_TX_T8P/DQ1T) ; also on sheet 19
M_P2B8: U11.B15(IO_7A_B15/DIFFIO_RX_T11N/DQ2T) ; also on sheet 19
M_P2B9: U11.C15(IO_7A_C15/DIFFIO_RX_T11P/DQ2T) ; also on sheet 19
M_P2C0: U11.E15(IO_7A_E15/DIFFIO_RX_T7P/DQ1T) ; also on sheet 19
M_P2C1: U11.F15(IO_7A_F15/DIFFIO_RX_T7N/DQ1T) ; also on sheet 19
M_P2C2: U11.G15(IO_7A_G15/DIFFIO_TX_T12P/DQ2T) ; also on sheet 19
M_P2C3: U11.B16(IO_7A_B16/DIFFIO_TX_T2P/DQ1T) ; also on sheet 19
M_P2C4: U11.C16(IO_7A_C16/DIFFIO_TX_T2N/DQ1T) ; also on sheet 19
M_P2C5: U11.E16(IO_7A_E16/DIFFIO_RX_T3N/DQ1T) ; also on sheet 19
M_P2C6: U11.G16(IO_7A_G16/DIFFIO_TX_T4N/DQ1T) ; also on sheet 19
M_P2C7: U11.H16(CLK11P_H16/DIFFIO_RX_T9P) ; also on sheet 19
M_P2C8: U11.G17(IO_7A_G17/DIFFIO_TX_T4P/DQ1T) ; also on sheet 19
M_P2C9: U11.G18(IO_7A_G18/DIFFIO_RX_T5P/DQS1T) ; also on sheet 19
M_PCLK1: U11.D17(IO_7A_D17/DIFFIO_RX_T3P/DQ1T) ; also on sheet 19
M_SCL0: J31.3 ; also on sheet 15
M_SCL1: J30.95(A48) J31.1 ; also on sheet 10 15 23 29
M_SCL2: R234.1 ; also on sheet 15
M_SDA0: J32.3 ; also on sheet 15
M_SDA1: J30.93(A47) J32.1 ; also on sheet 10 15 23 29
M_SDA2: R235.1 ; also on sheet 15
MSEL0: R42.2 R46.1 U11.L6(MSEL0)
MSEL1: R43.2 R47.1 U11.J6(MSEL1)
MSEL2: R48.1 U11.A2(MSEL2)
MSEL3: R49.1 U11.E5(MSEL3)
MSEL4: R44.2 U11.F3(MSEL4)
nCONFIG: R39.2 TP11.1 U11.A4(NCONFIG)
nSTATUS: R40.2 TP12.1 U11.H5(NSTATUS)
P1_HSYNC: J30.86(B43) R241.2
P1_VSYNC: J30.55(A28) RP16.6
P1P1V: C320.1 C321.1 L1.2 R179.1 TP63.1 ; also on sheet 26 27 28
P1P8V: C323.1 L2.2 R180.1 TP64.1 ; also on sheet 13 25 27 28
P1P8V_A: C339.1 TP66.1 U29.7(OUT7) U29.8(OUT8) ; also on sheet 27 28
P1P8V_ITEA: C348.1 TP69.1 U32.3(VOUT) ; also on sheet 25
P2_HSYNC: J30.46(B23) R240.1
P2P5V_FAUXPLL: C344.1 TP68.1 U31.5(OUT) ; also on sheet 26
P3P3V: C64.1 C334.1 C340.1 C343.1 C346.1 C347.1 L3.2 R41.1 R52.1 R53.1 R54.1 R174.1 R175.1 R189.1 R191.1 R196.1 TP65.1 U12.8(VCC) U29.5(IN5) U29.6(IN6) U31.1(IN) U32.1(VIN) ; also on sheet 8 9 10 11 12 13 14 15 16 17 18 19 23 25 27 28 29
P_CLK1: J30.54(B27) RP17.6
P_CLK2: J30.14(B7) R239.1
P_CLK3: J30.119(A60) R238.2
PCLK: R238.1 R239.2 U11.N9(CLK1P_N9/DIFFIO_RX_B23P) ; also on sheet 23
S_3DLR_GPIO78: U11.T19(RZQ_1_T19/DIFFIO_TX_R1P/DQ1R) ; also on sheet 12
S_P1A0: U11.H18(IO_7A_H18/DIFFIO_RX_T5N/DQSN1T) ; also on sheet 12
S_P1A1: U11.J18(IO_7A_J18/DIFFIO_TX_T6N/DQ1T) ; also on sheet 12
S_P1A2: U11.J19(IO_7A_J19/DIFFIO_TX_T6P) ; also on sheet 12
S_P1A3: U11.K16(IO_7A_K16/DIFFIO_TX_T10N/DQ2T) ; also on sheet 12
S_P1A4: U11.K17(IO_5B_K17/DIFFIO_RX_R13P/DQS2R) ; also on sheet 12
S_P1A5: U11.K19(IO_7A_K19/DIFFIO_RX_T1N) ; also on sheet 12
S_P1A6: U11.K20(IO_7A_K20/DIFFIO_RX_T1P) ; also on sheet 12
S_P1A7: U11.K21(IO_5B_K21/DIFFIO_TX_R16P/DQ2R) ; also on sheet 12
S_P1A8: U11.K22(IO_5B_K22/DIFFIO_TX_R16N) ; also on sheet 12
S_P1A9: U11.L17(IO_5B_L17/DIFFIO_RX_R13N/DQSN2R) ; also on sheet 12
S_P1B0: U11.L18(IO_5B_L18/DIFFIO_RX_R15N/DQ2R) ; also on sheet 12
S_P1B1: U11.L19(IO_5B_L19/DIFFIO_RX_R15P/DQ2R) ; also on sheet 12
S_P1B2: U11.L22(IO_5B_L22/FPLL_BR_CLKOUT1,FPLL_BR_CLKOUTN/DIFFIO_TX_R12N/DQ2R) ; also on sheet 12
S_P1B3: U11.M16(CLK6N_M16/DIFFIO_RX_R9N) ; also on sheet 12
S_P1B4: U11.M18(IO_5B_M18/DIFFIO_RX_R11N/DQ2R) ; also on sheet 12
S_P1B5: U11.M20(IO_5B_M20/DIFFIO_TX_R14P) ; also on sheet 12
S_P1B6: U11.M21(IO_5B_M21/DIFFIO_TX_R14N/DQ2R) ; also on sheet 12
S_P1B7: U11.M22(IO_5B_M22/FPLL_BR_CLKOUT0,FPLL_BR_CLKOUTP,FPLL_BR_FB/DIFFIO_TX_R12P/DQ2R) ; also on sheet 12
S_P1B8: U11.N19(IO_5B_N19/DIFFIO_RX_R11P/DQ2R) ; also on sheet 12
S_P1B9: U11.N20(IO_5B_N20/DIFFIO_TX_R10P/DQ2R) ; also on sheet 12
S_P1C0: U11.N21(IO_5B_N21/DIFFIO_TX_R10N/DQ2R) ; also on sheet 12
S_P1C1: U11.P16(IO_5A_P16/DIFFIO_RX_R8P/DQ1R) ; also on sheet 12
S_P1C2: U11.P17(IO_5A_P17/DIFFIO_RX_R8N/DQ1R) ; also on sheet 12
S_P1C3: U11.P18(IO_5A_P18/DIFFIO_TX_R7N) ; also on sheet 12
S_P1C4: U11.P19(IO_5A_P19/DIFFIO_TX_R7P/DQ1R) ; also on sheet 12
S_P1C5: U11.P22(IO_5A_P22/DEV_CLRN/DIFFIO_TX_R5N/DQ1R) ; also on sheet 12
S_P1C6: U11.R15(IO_5A_R15/DIFFIO_RX_R4N/DQ1R) ; also on sheet 12
S_P1C7: U11.R16(IO_5A_R16/DIFFIO_RX_R6P/DQS1R) ; also on sheet 12
S_P1C8: U11.R17(IO_5A_R17/DIFFIO_RX_R6N/DQSN1R) ; also on sheet 12
S_P1C9: U11.R21(IO_5A_R21/DEV_OE/DIFFIO_TX_R5P) ; also on sheet 12
S_P1DATEN: U11.R22(IO_5A_R22/CVP_CONFDONE/DIFFIO_TX_R3N/DQ1R) ; also on sheet 12
S_P1HS: U11.T15(IO_5A_T15/DIFFIO_RX_R4P/DQ1R) ; also on sheet 12
S_P1VS: U11.T17(IO_5A_T17/CRC_ERROR/DIFFIO_RX_R2N) ; also on sheet 12
S_P2A0: U11.T20(IO_5A_T20/PR_REQUEST/DIFFIO_TX_R1N/DQ1R) ; also on sheet 12
S_P2A1: U11.T22(IO_5A_T22/NCEO/DIFFIO_TX_R3P/DQ1R) ; also on sheet 12
S_P2A2: U11.U22(IO_4A_U22/DIFFIO_TX_B45N/DQ6B) ; also on sheet 12
S_P2A3: U11.W22(IO_4A_W22/DIFFIO_TX_B41P/DQ6B) ; also on sheet 12
S_P2A4: U11.Y22(IO_4A_Y22/DIFFIO_TX_B41N) ; also on sheet 12
S_P2A5: U11.AA22(IO_4A_AA22/DIFFIO_TX_B40P/DQ5B) ; also on sheet 12
S_P2A6: U11.AB22(IO_4A_AB22/DIFFIO_TX_B40N/DQ5B) ; also on sheet 12
S_P2A7: U11.U21(IO_4A_U21/DIFFIO_TX_B48N/DQ6B) ; also on sheet 12
S_P2A8: U11.V21(IO_4A_V21/DIFFIO_TX_B45P/DQ6B) ; also on sheet 12
S_P2A9: U11.W21(IO_4A_W21/DIFFIO_TX_B44P) ; also on sheet 12
S_P2B0: U11.Y21(IO_4A_Y21/DIFFIO_TX_B44N/DQ6B) ; also on sheet 12
S_P2B1: U11.AB21(IO_4A_AB21/DIFFIO_TX_B33P/DQ5B) ; also on sheet 12
S_P2B2: U11.U20(IO_4A_U20/DIFFIO_TX_B48P/DQ6B) ; also on sheet 12
S_P2B3: U11.V20(IO_4A_V20/DIFFIO_RX_B38N/DQ5B) ; also on sheet 12
S_P2B4: U11.Y20(IO_4A_Y20/DIFFIO_RX_B42N/DQ6B) ; also on sheet 12
S_P2B5: U11.AA20(IO_4A_AA20/DIFFIO_TX_B37P/DQ5B) ; also on sheet 12
S_P2B6: U11.AB20(IO_4A_AB20/DIFFIO_TX_B33N) ; also on sheet 12
S_P2B7: U11.V19(IO_4A_V19/DIFFIO_RX_B46N/DQ6B) ; also on sheet 12
S_P2B8: U11.W19(IO_4A_W19/DIFFIO_RX_B38P/DQ5B) ; also on sheet 12
S_P2B9: U11.Y19(IO_4A_Y19/DIFFIO_RX_B42P/DQ6B) ; also on sheet 12
S_P2C0: U11.AA19(IO_4A_AA19/DIFFIO_TX_B37N/DQ5B) ; also on sheet 12
S_P2C1: U11.V18(IO_4A_V18/DIFFIO_RX_B46P/DQ6B) ; also on sheet 12
S_P2C2: U11.AA18(IO_4A_AA18/DIFFIO_TX_B36P) ; also on sheet 12
S_P2C3: U11.AB18(IO_4A_AB18/DIFFIO_TX_B32P/DQ4B) ; also on sheet 12
S_P2C4: U11.U17(IO_4A_U17/DIFFIO_RX_B47P) ; also on sheet 12
S_P2C5: U11.Y17(IO_4A_Y17/DIFFIO_RX_B34P/DQ5B) ; also on sheet 12
S_P2C6: U11.AA17(IO_4A_AA17/DIFFIO_TX_B36N/DQ5B) ; also on sheet 12
S_P2C7: U11.AB17(IO_4A_AB17/DIFFIO_TX_B32N/DQ4B) ; also on sheet 12
S_P2C8: U11.V16(CLK3N_V16/DIFFIO_RX_B39N) ; also on sheet 12
S_P2C9: U11.Y16(IO_4A_Y16/DIFFIO_RX_B34N/DQ5B) ; also on sheet 12
S_PCLK1: U11.T18(IO_5A_T18/INIT_DONE/DIFFIO_RX_R2P) ; also on sheet 12
SSP0_CLK: U11.D3(IO_2A_D3/DIFFIO_RX_L11P/DQS1L) ; also on sheet 8 11 18
SSP0_CSZ2_FPGA: U11.C2(IO_2A_C2/DIFFIO_TX_L9P/DQ1L) ; also on sheet 18
SSP0_RXD_S2M: U11.G1(IO_2A_G1/DIFFIO_RX_L10N/DQ1L) ; also on sheet 8 11 18
SSP0_TXD_M2S: U11.C1(IO_2A_C1/DIFFIO_TX_L9N) ; also on sheet 8 11 18
UART1_RXD: J30.92(B46) RP18.8
N20556337: C327.1 R182.2
N20557124: C330.1 R184.2
N20590731: D5.2(ANODE) R41.2
N20590733: Q1.G R45.2
N20590858: D5.1(CATHODE) Q1.D
N20778960: C337.1 R193.2
N22208593: J30.114(B57) R235.2
N22214053: J30.1(A1) R233.2
N22214096: J30.15(A8) R237.2
N22214444: J30.113(A57) R234.2
N22215217: J30.13(A7) R236.2
N22228652: J30.115(A58) J31.2
N22228678: J30.117(A59) J32.2
N22305376: C376.1 U49.8(SS/TR)
N22305567: R249.2 R250.1 U49.6(FB)

Not connected (* = marked no-connect by the designer): J5 6* 7* 8*; J30 2(B1)* 3(A2)* 4(B2)* 5(A3)* 6(B3)* 7(A4)* 8(B4)* 10(B5)* 12(B6)* 47(A24)* 48(B24)* 53(A27)* 96(B48)* 97(A49)* 98(B49)* 99(A50)* 100(B50)* 101(A51)* 102(B51)* 103(A52)* 104(B52)* 105(A53)* 106(B53)* 107(A54)* 109(A55)* 110(B55)* 111(A56)* 112(B56)* 116(B58)* 118(B59)* 120(B60)*; RP16 4* 5*; RP17 4* 5*; RP18 3* 4* 5* 6*; U11 AA5(AS_DATA2_3A_AA5/DATA2)* H15(CLK11N_H15/DIFFIO_RX_T9N)* K7(IO_8A_K7/DIFFIO_TX_T26N/DQ4T)* L7(IO_8A_L7/DIFFIO_TX_T26P/DQ4T)* L8(IO_7A_L8/DIFFIO_TX_T22P)* M6(IO_3A_M6/PR_DONE/DIFFIO_RX_B7N)* M7(IO_3A_M7/PR_ERROR/DIFFIO_RX_B7P)* M8(IO_3B_M8/CLK0N,FPLL_BL_FBN/DIFFIO_RX_B15N)* N1(IO_2A_N1/DIFFIO_TX_L13N/DQ1L)* N2(IO_2A_N2/DIFFIO_TX_L13P/DQ1L)* N6(IO_3A_N6/DATA12/DIFFIO_RX_B3P/DQS1B)* N16(CLK6P_N16/DIFFIO_RX_R9P)* P9(CLK1N_P9/DIFFIO_RX_B23N)* R5(IO_3A_R5/DATA8/DIFFIO_RX_B1P/DQ1B)* R6(IO_3A_R6/DATA6/DIFFIO_RX_B1N/DQ1B)* T4(AS_DATA3_3A_T4/DATA3)* V15(CLK2P_V15/DIFFIO_RX_B31P)*; U29 1(NC)*

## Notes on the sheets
sheet 1
- DO NOT INSTALL
- DO NOT INSTALL
- NOTE:
  DO NOT INSTALL WITH
  HDMI/TFP503 ADC PCB
- DAUGHTER CARD I2C CLOCK
- NOTE:
  DO NOT INSTALL WITH
  HDMI/TFP503 ADC PCB
- Default: Jumper Pin 2 to Pin 3
- DO NOT INSTALL
- DAUGHTER CARD I2C DATA
- Default: Jumper Pin 2 to Pin 3
- External Parallel Video Input Connector
- TI Information
           Selective Disclosure
  Property of Texas Instruments Only
sheet 2
- IMPORTANT NOTICE FOR TI REFERENCE DESIGNS
- Texas Instruments Incorporated ("TI") reference designs are solely intended to assist designers (“Buyers”) who are developing systems that incorporate TI semiconductor products (also referred to herein
  as “components”). Buyer understands and agrees that Buyer remains responsible for using its independent analysis, evaluation and judgment in designing Buyer’s systems and products.
  TI reference designs have been created using standard laboratory conditions and engineering practices. TI has not conducted any testing other than that specifically described in the published documentation
  for a particular reference design. TI may make corrections, enhancements, improvements and other changes to its reference designs.
  Buyers are authorized to use TI reference designs with the TI component(s) identified in each particular reference design and to modify the reference design in the development of their end products.
  HOWEVER, NO OTHER LICENSE, EXPRESS OR IMPLIED, BY ESTOPPEL OR OTHERWISE TO ANY OTHER TI INTELLECTUAL PROPERTY RIGHT, AND NO LICENSE TO ANY
  THIRD PARTY TECHNOLOGY OR INTELLECTUAL PROPERTY RIGHT, IS GRANTED HEREIN, including but not limited to any patent right, copyright, mask work right, or other intellectual property
  right relating to any combination, machine, or process in which TI components or services are used. Information published by TI regarding third-party products or services does not constitute a license to
  use such products or services, or a warranty or endorsement thereof. Use of such information may require a license from a third party under the patents or other intellectual property of the third
  party, or a license from TI under the patents or other intellectual property of TI.
  TI REFERENCE DESIGNS ARE PROVIDED "AS IS". TI MAKES NO WARRANTIES OR REPRESENTATIONS WITH REGARD TO THE REFERENCE DESIGNS OR USE OF
  THE REFERENCE DESIGNS, EXPRESS, IMPLIED OR STATUTORY, INCLUDING ACCURACY OR COMPLETENESS. TI DISCLAIMS ANY WARRANTY OF TITLE AND
  ANY IMPLIED WARRANTIES OF MERCHANTABILITY, FITNESS FOR A PARTICULAR PURPOSE, QUIET ENJOYMENT, QUIET POSSESSION, AND NON-INFRINGEMENT
  OF ANY THIRD PARTY INTELLECTUAL PROPERTY RIGHTS WITH REGARD TO TI REFERENCE DESIGNS OR USE THEREOF. TI SHALL NOT BE LIABLE FOR AND SHALL
  NOT DEFEND OR INDEMNIFY BUYERS AGAINST ANY THIRD PARTY INFRINGEMENT CLAIM THAT RELATES TO OR IS BASED ON A COMBINATION OF COMPONENTS
  PROVIDED IN A TI REFERENCE DESIGN. IN NO EVENT SHALL TI BE LIABLE FOR ANY ACTUAL, SPECIAL, INCIDENTAL, CONSEQUENTIAL OR INDIRECT DAMAGES,
  HOWEVER CAUSED, ON ANY THEORY OF LIABILITY AND WHETHER OR NOT TI HAS BEEN ADVISED OF THE POSSIBILITY OF SUCH DAMAGES, ARISING IN ANY WAY
  OUT OF TI REFERENCE DESIGNS OR BUYER’S USE OF TI REFERENCE DESIGNS.
  TI reserves the right to make corrections, enhancements, improvements and other changes to its semiconductor products and services per JESD46, latest issue, and to discontinue any product or
  service per JESD48, latest issue. Buyers should obtain the latest relevant information before placing orders and should verify that such information is current and complete. All semiconductor products
  are sold subject to TI’s terms and conditions of sale supplied at the time of order acknowledgment.
  TI warrants performance of its components to the specifications applicable at the time of sale, in accordance with the warranty in TI’s terms and conditions of sale of semiconductor products.
  Testing and other quality control techniques for TI components are used to the extent TI deems necessary to support this warranty. Except where mandated by applicable law,
  testing of all parameters of each component is not necessarily performed.
  TI assumes no liability for applications assistance or the design of Buyers’ products. Buyers are responsible for their products and applications using TI components. To minimize the risks
  associated with Buyers’ products and applications, Buyers should provide adequate design and operating safeguards.
  Reproduction of significant portions of TI information in TI data books, data sheets or reference designs is permissible only if reproduction is without alteration and is accompanied by all associated
  warranties, conditions, limitations, and notices. TI is not responsible or liable for such altered documentation. Information of third parties may be subject to additional restrictions.
  Buyer acknowledges and agrees that it is solely responsible for compliance with all legal, regulatory and safety-related requirements concerning its products, and any use of TI components in its
  applications, notwithstanding any applications-related information or support that may be provided by TI. Buyer represents and agrees that it has all the necessary expertise to create
  and implement safeguards that anticipate dangerous failures, monitor failures and their consequences, lessen the likelihood of dangerous failures and take appropriate remedial actions.
  Buyer will fully indemnify TI and its representatives against any damages arising out of the use of any TI components in Buyer’s safety-critical applications.
  In some cases, TI components may be promoted specifically to facilitate safety-related applications. With such components, TI’s goal is to help enable customers to design and create their own
  end-product solutions that meet applicable functional safety standards and requirements. Nonetheless, such components are subject to these terms.
  No TI components are authorized for use in FDA Class III (or similar life-critical medical equipment) unless authorized officers of the parties have executed an agreement specifically governing such use.
  Only those TI components that TI has specifically designated as military grade or “enhanced plastic” are designed and intended for use in military/aerospace applications or environments. Buyer
  acknowledges and agrees that any military or aerospace use of TI components that have not been so designated is solely at Buyer's risk, and Buyer is solely responsible for compliance with all
  legal and regulatory requirements in connection with such use.
  TI has specifically designated certain components as meeting ISO/TS16949 requirements, mainly for automotive use. In any case of use of non-designated products, TI will not be responsible for any
  failure to meet ISO/TS16949.
- Important Notice
- TI Information
           Selective Disclosure
  Property of Texas Instruments Only
sheet 3
- 3.3V to 1.8V @250mA LDO
  for controller 1.8V analog
- 12V to 3V @500mA
  for FPGA Vccio
- 3.3V to 2.5V @150mA LDO
  for FPGA 2.5V AUX/PLL power
- Distribute ground vias around PCB
- 3.3V to 1.8V @1A LDO
  for HDMI Rx 1.8V analog
- Left/Right Split FPGA Power Generation VCCIO, 1.8V & 2.5V LDOs
- TI Information
           Selective Disclosure
  Property of Texas Instruments Only
sheet 4
- MSEL 4:0
  10011 = active serial standard POR
  10010 = active serial fast POR
- D
- FDV303N
- G
- S
- Use Altera's "Serial loader" option to update flash
  thru the FPGA JTAG port with Byteblaster cable
- Altera's USB ByteBlaster Connector
- Left/Right Split FPGA Configuration
- TI Information
           Selective Disclosure
  Property of Texas Instruments Only
sheet 5
- Left/Right Split FPGA Bank 5A, 5B, 7A, 8A
- TI Information
           Selective Disclosure
  Property of Texas Instruments Only
sheet 6
- JTAG pins are powered
  by Vccpd of Bank 3A
- Left/Right Split FPGA Bank 2A, 3A, 3B, 4A
- TI Information
           Selective Disclosure
  Property of Texas Instruments Only
sheet 7
- 12V to 1.12V @6A
  Switching Freq ~ 700KHz
  Vstart/stop ~ 6.08V/5.57V
  SS ~ 3.5ms
- 12V to 1.8V @3A
  Switching Freq ~ 750KHz
  Vstart/stop ~ 8.44V/7.95V
  SS ~ 15ms
- 12V to 3.3V @5A
  Switching Freq ~ 750KHz
  Vstart/stop ~ 8.44V/7.95V
  SS ~ 15ms
- Power Generation 1.1V, 1.8V and 3.3V
- TI Information
           Selective Disclosure
  Property of Texas Instruments Only
